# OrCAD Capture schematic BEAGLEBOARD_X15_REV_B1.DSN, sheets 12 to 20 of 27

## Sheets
12 P12_AM572x ETHERNET 1: size B; title: BeagleBoard-X15 ETHERNET PORT 1; note: BeagleBoard-X15_B.dsn
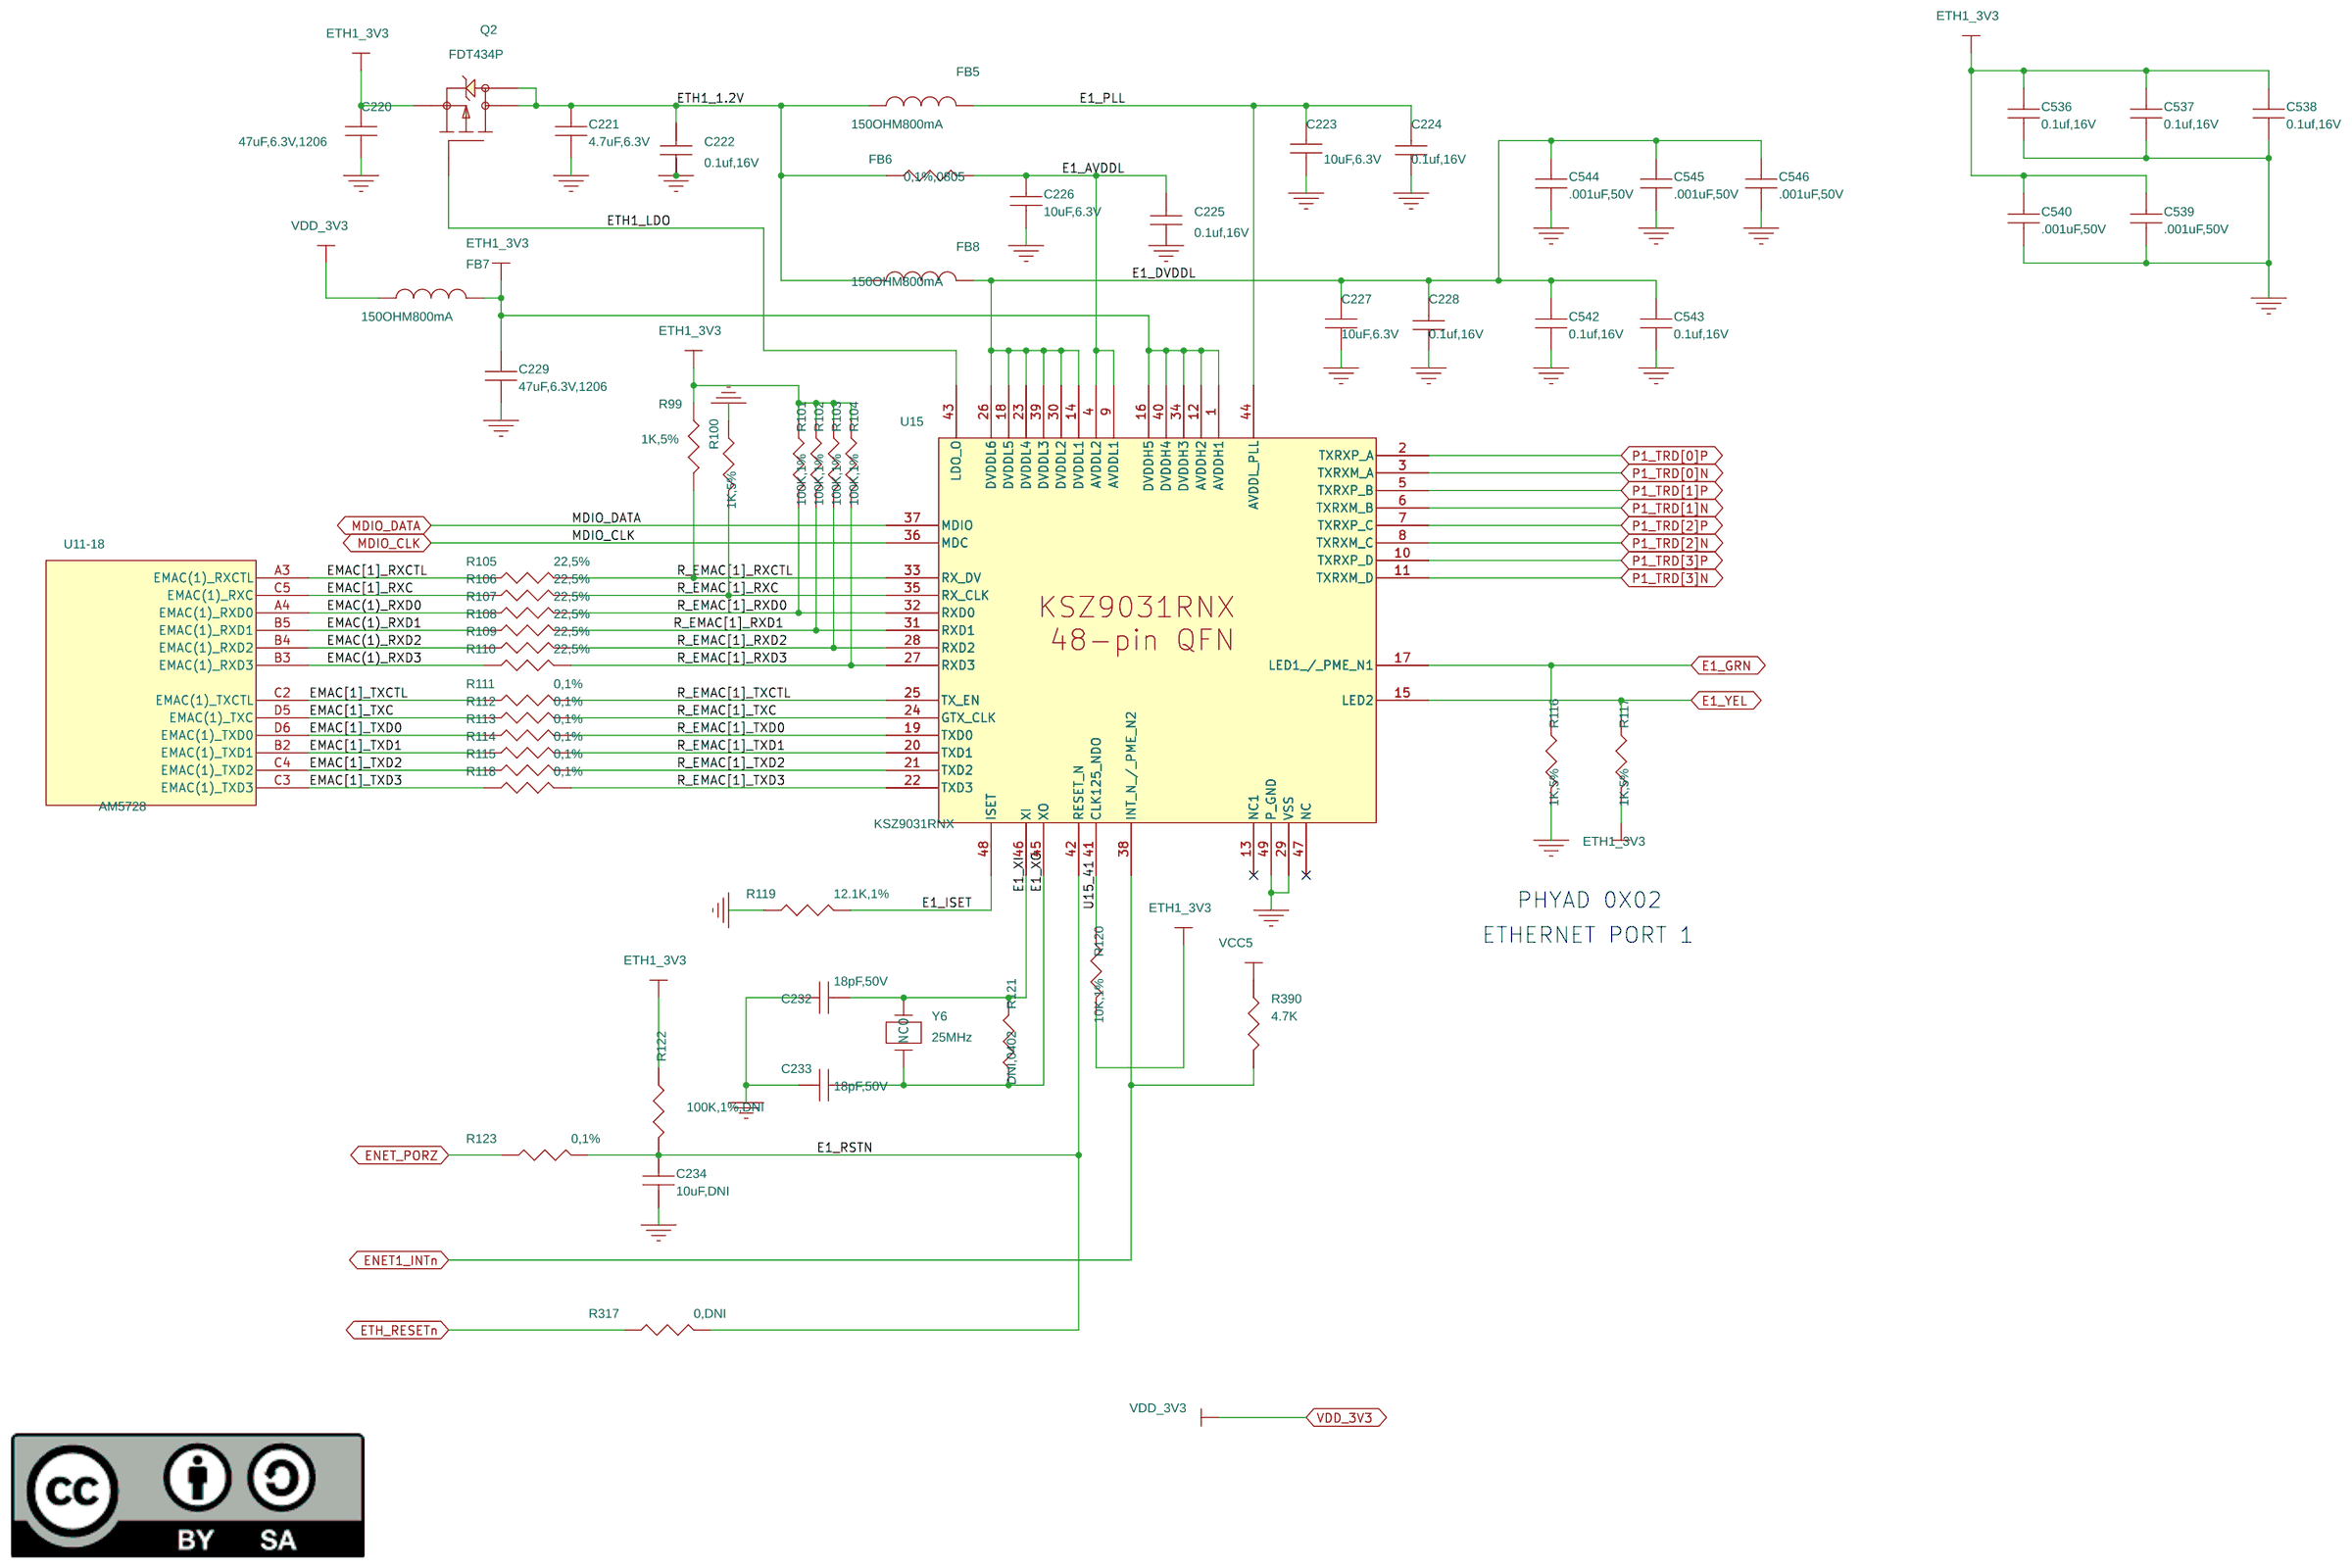
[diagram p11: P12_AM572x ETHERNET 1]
13 P13_AM572x VIN3A, LCD, BOOT: size B; title: BeagleBoard-X15 I/0, LCD, & BOOT; note: BeagleBoard-X15_B.dsn
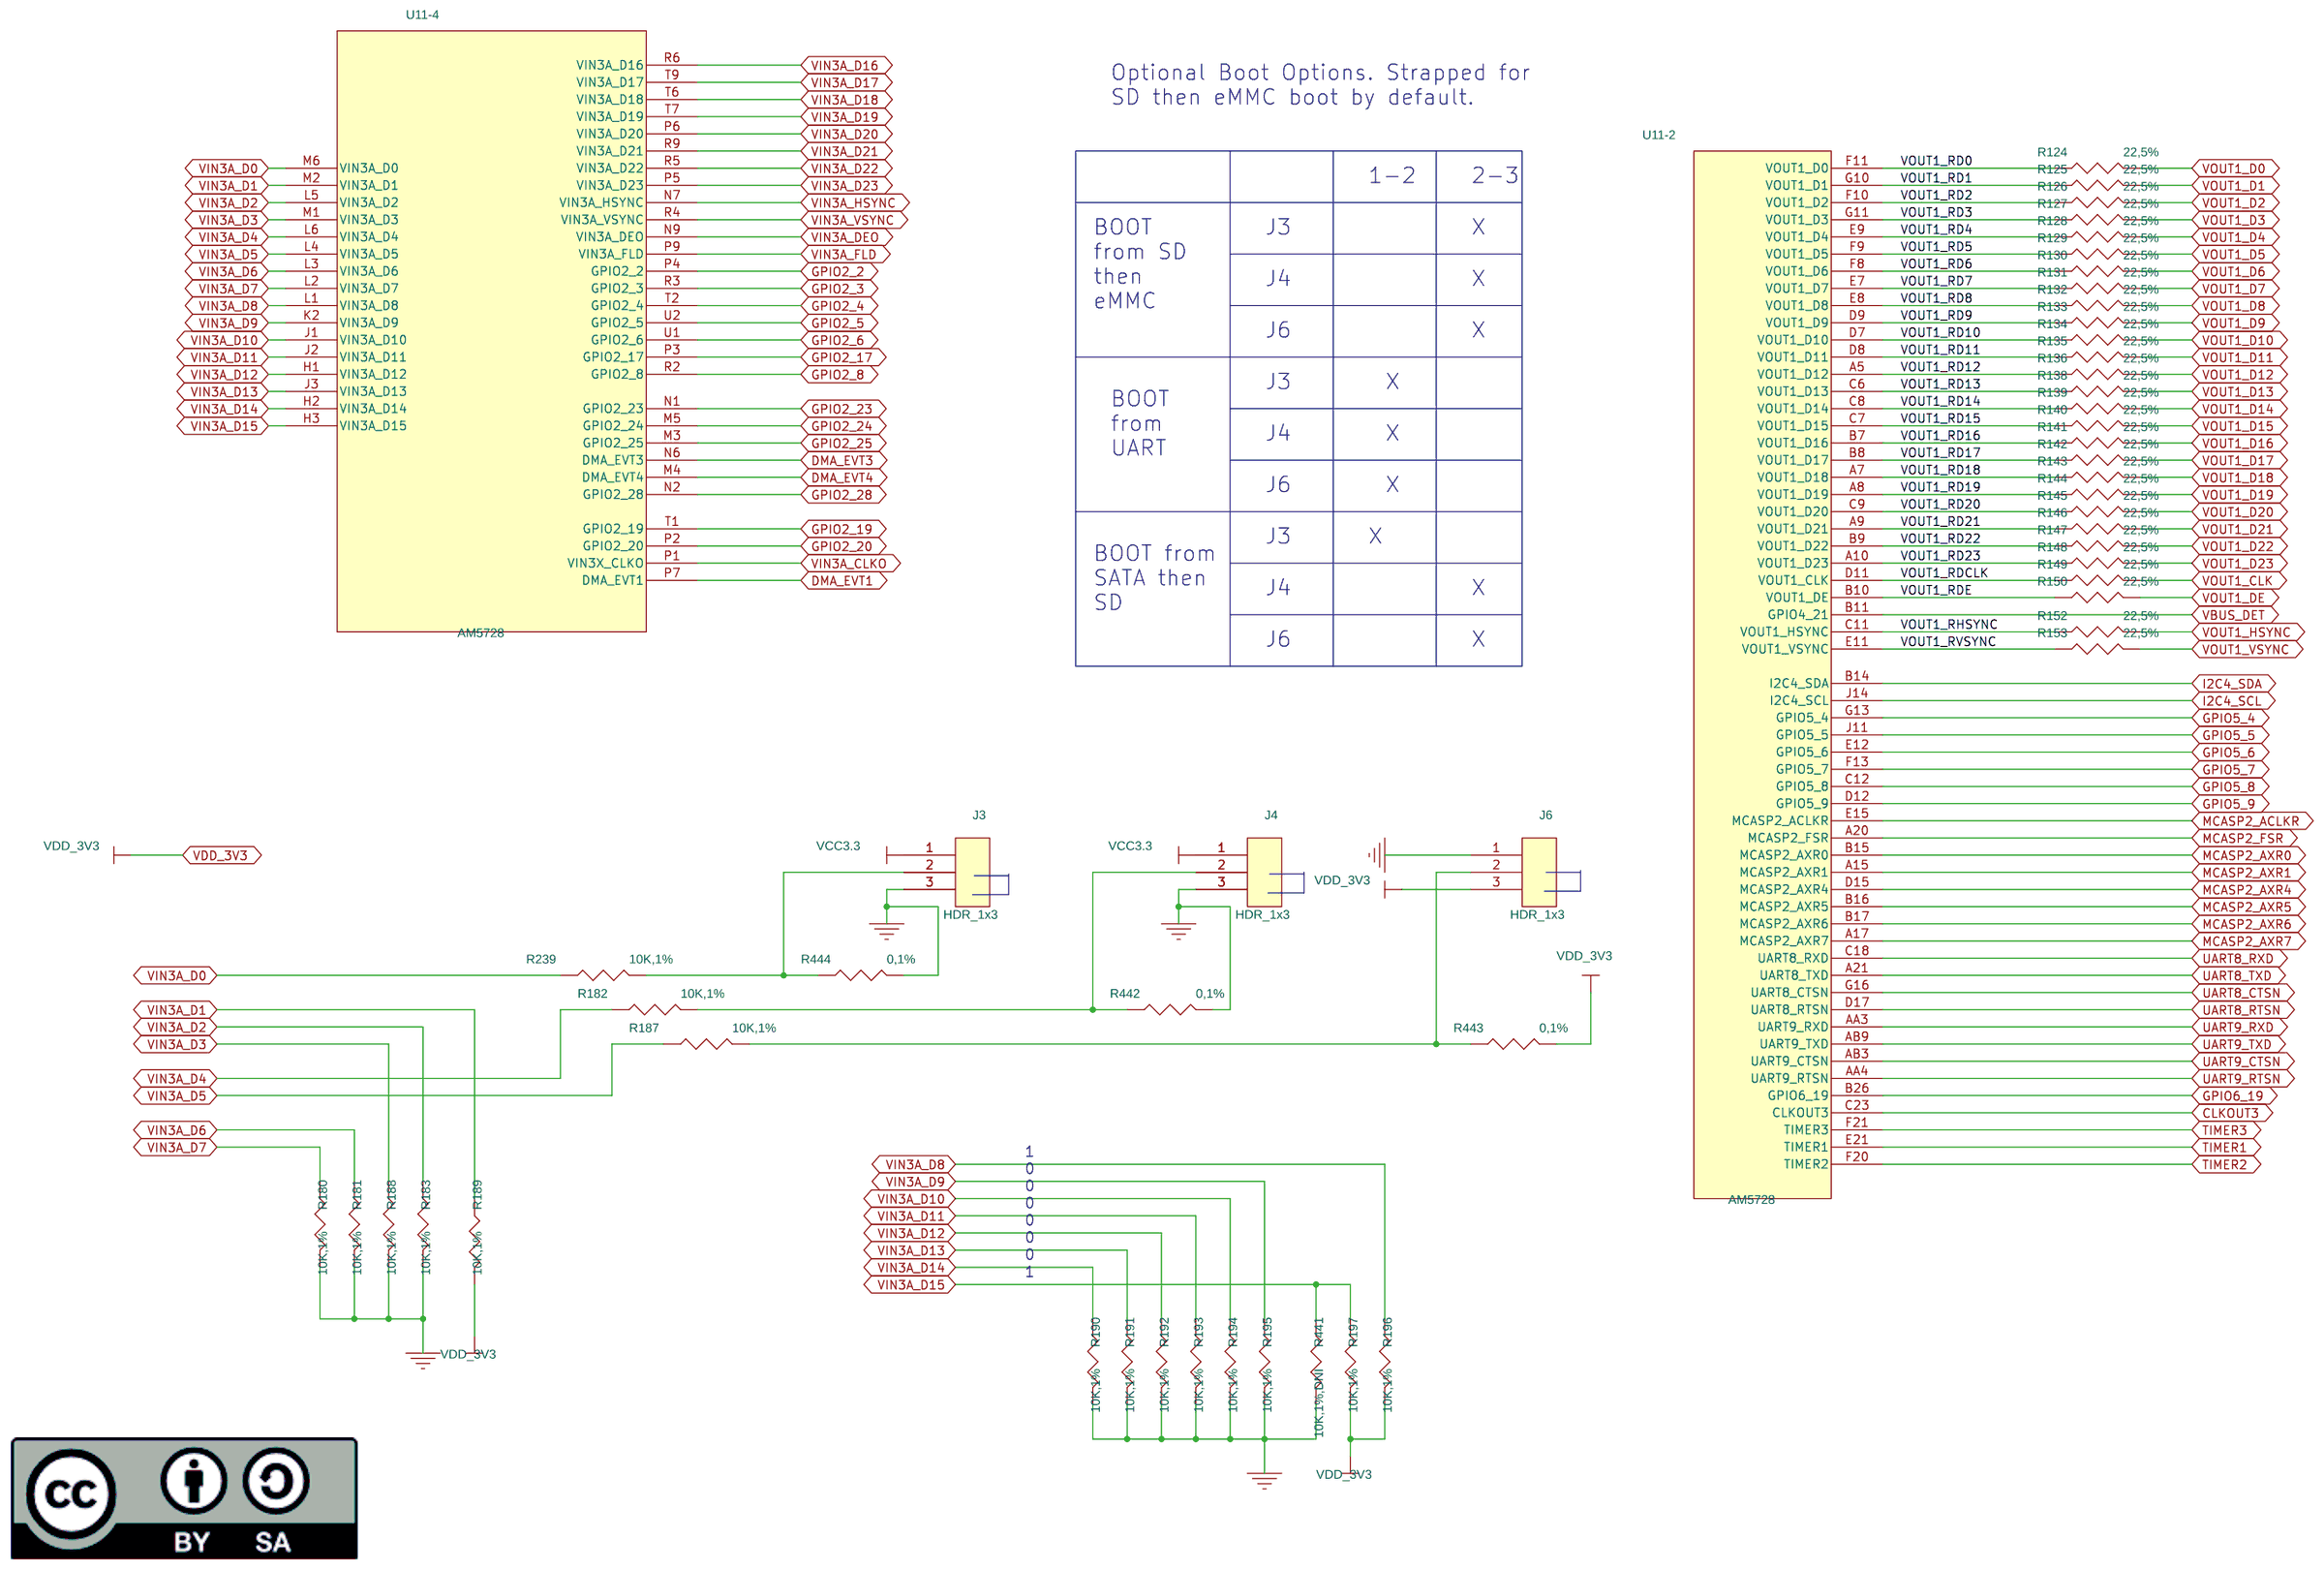
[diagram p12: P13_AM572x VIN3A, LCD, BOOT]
14 P14 AM572x USB PORTS & HUB: size B; title: BeagleBoard-X15 AM572x USB INTERFACES; note: BeagleBoard-X15_B.dsn
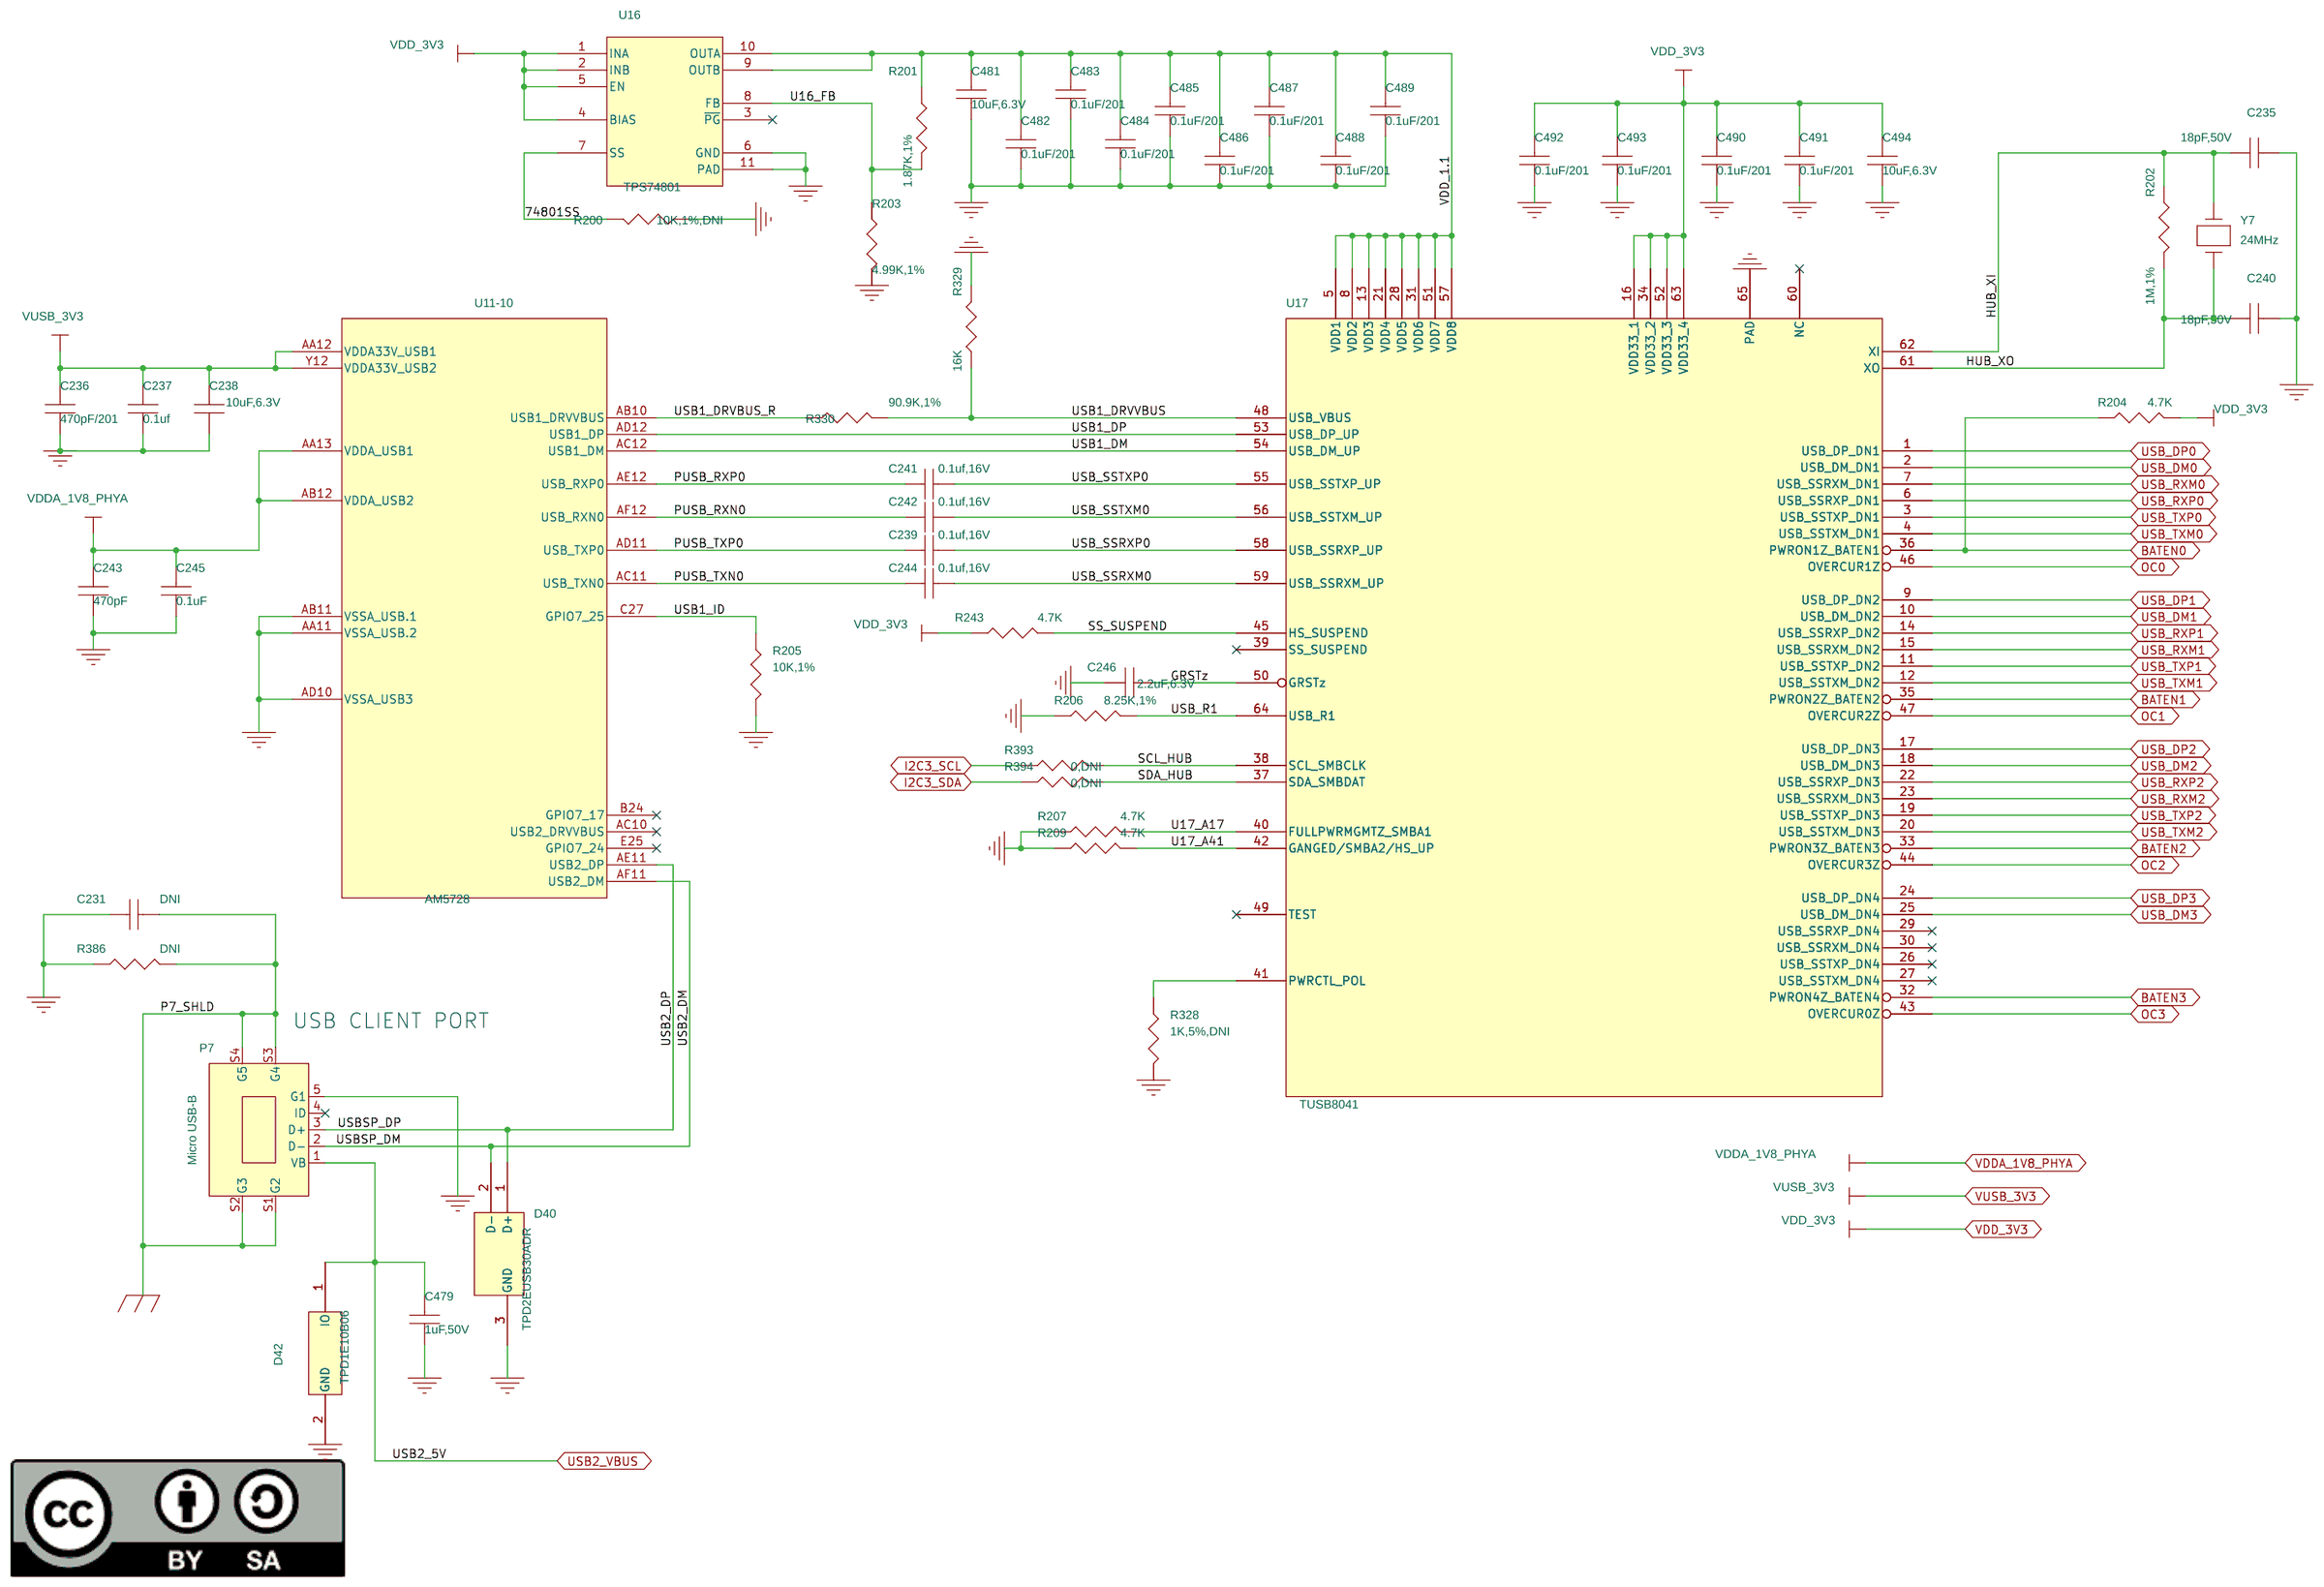
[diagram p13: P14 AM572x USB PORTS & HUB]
15 P16_AM572x, AUDIO, & DEBUG: size B; title: BeagleBoard-X15 AUDIO CODEC & DEBUG PORT; note: BeagleBoard-X15_B.dsn
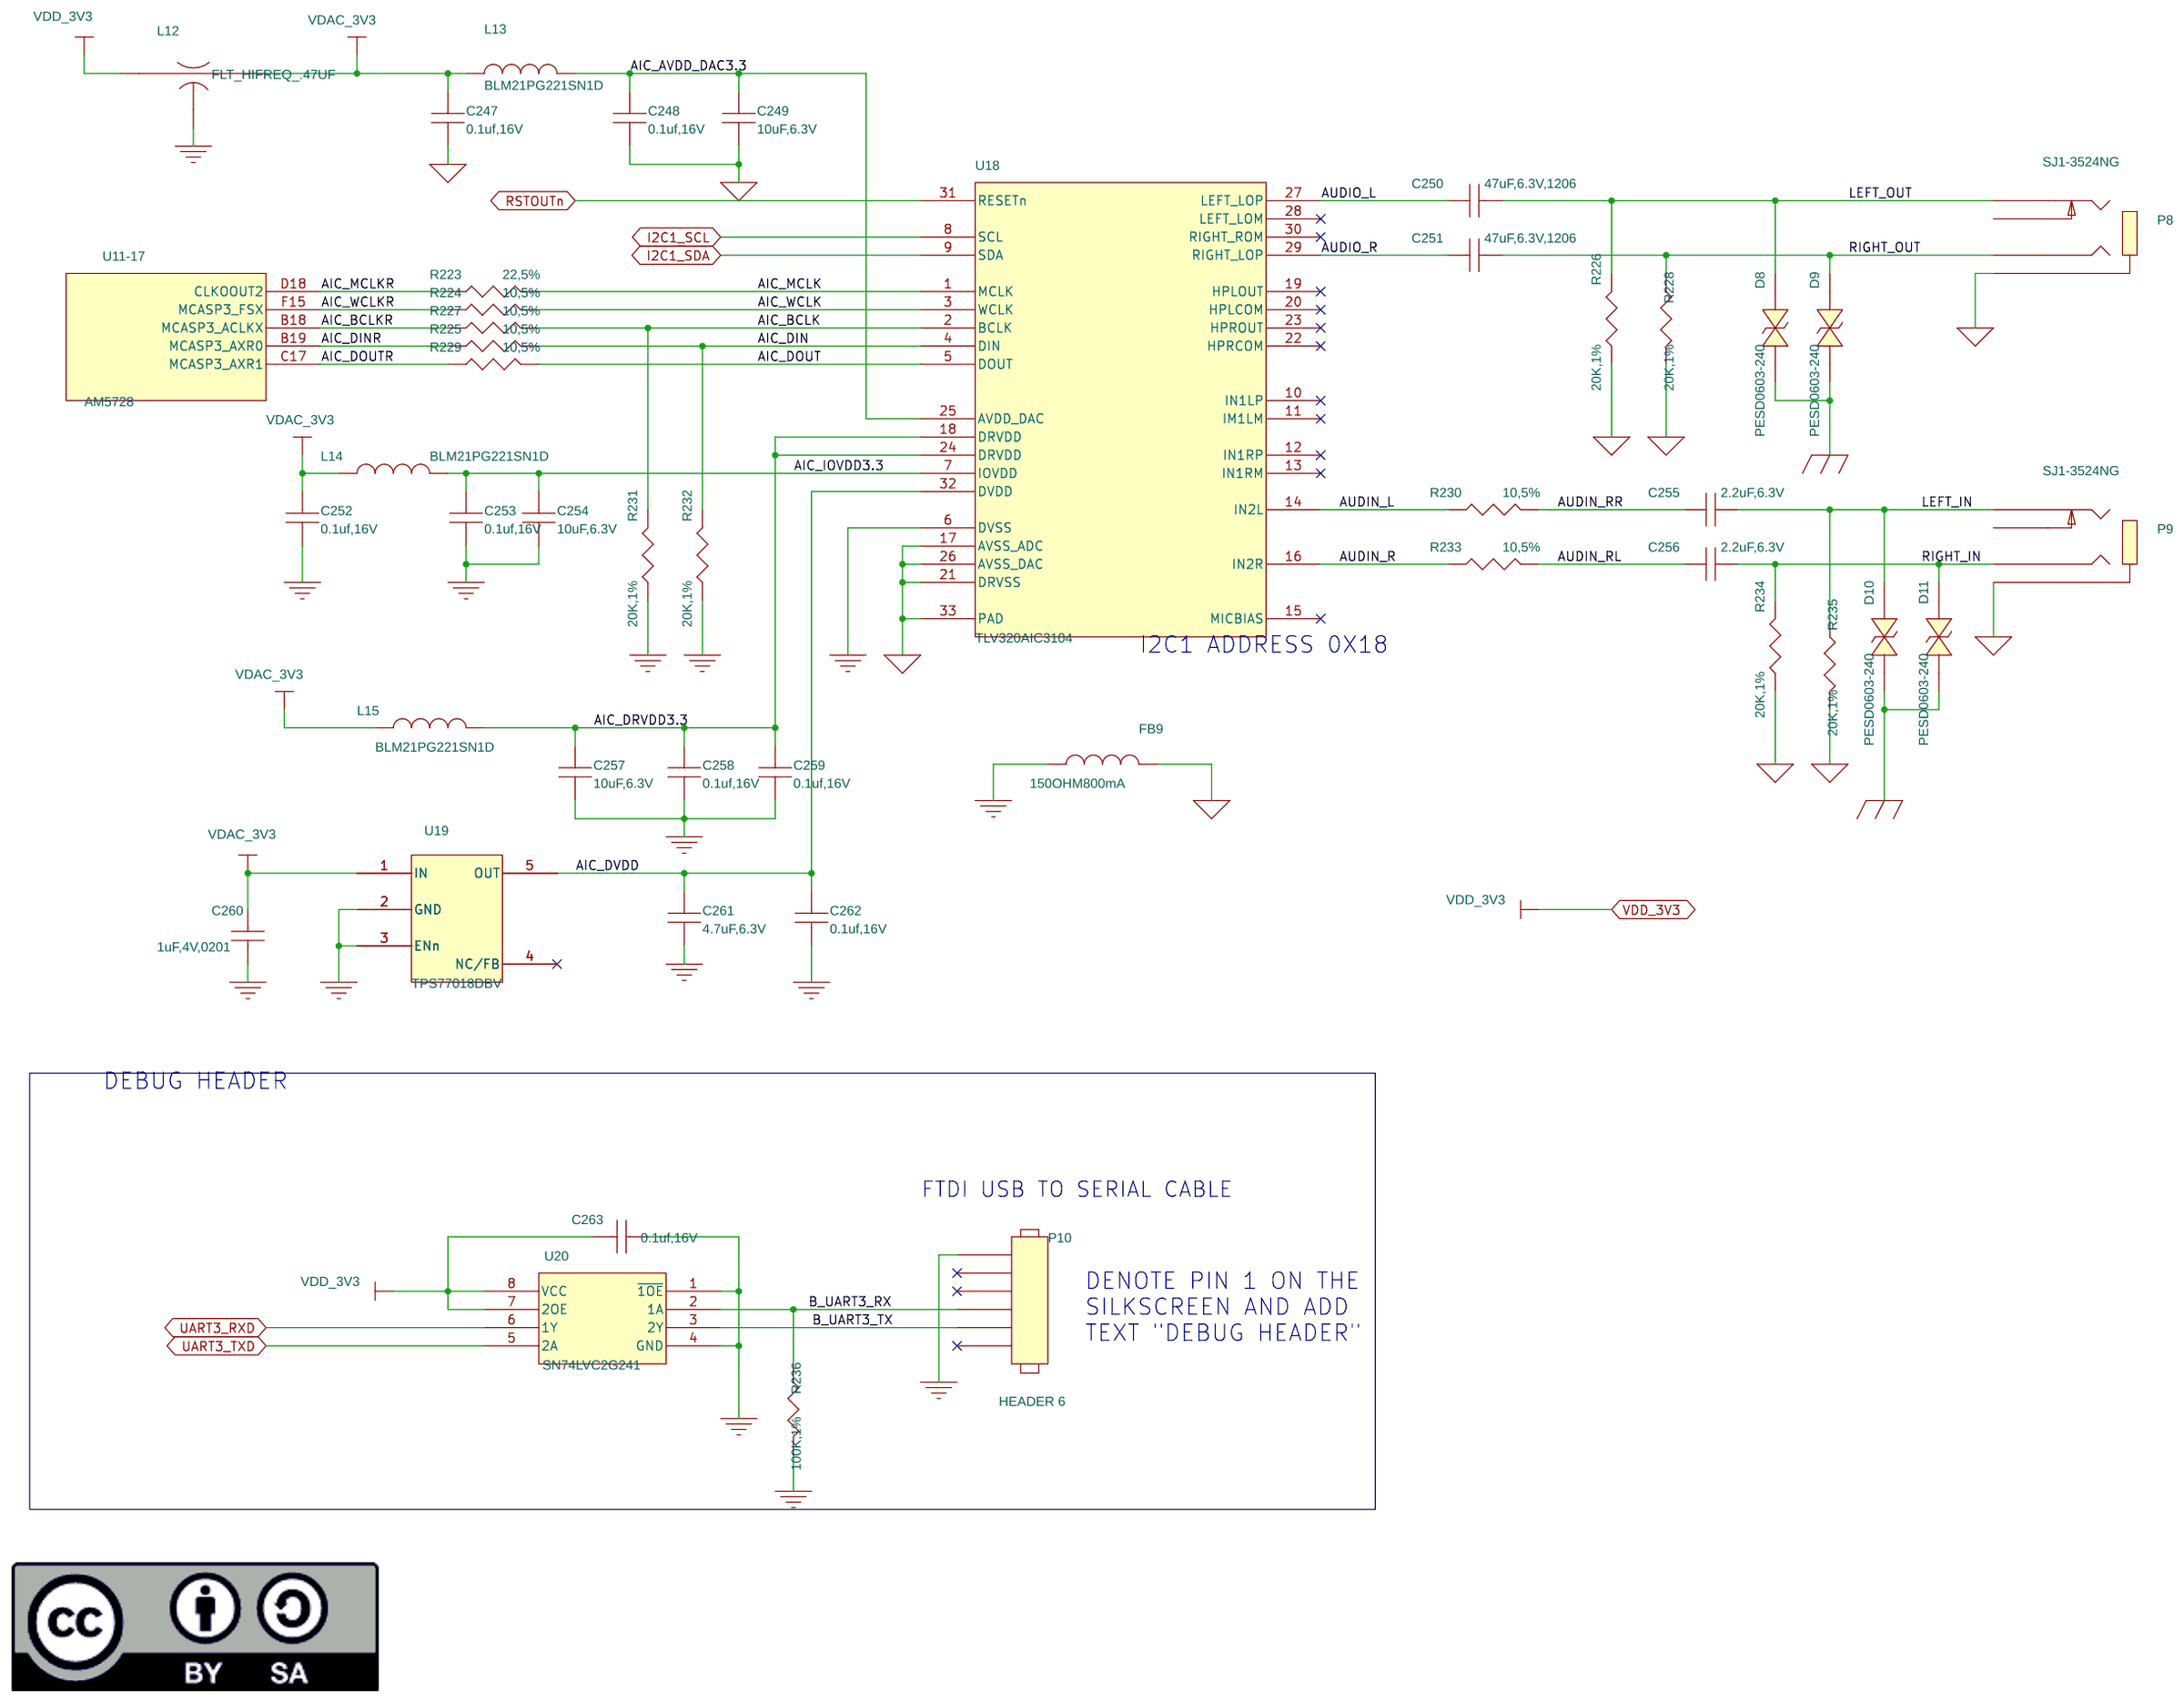
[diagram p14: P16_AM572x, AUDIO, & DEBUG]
16 P17_AM572x_HDMI PORT: size B; title: BeagleBoard-X15 HDMI PORT; note: BeagleBoard-X15_B.dsn
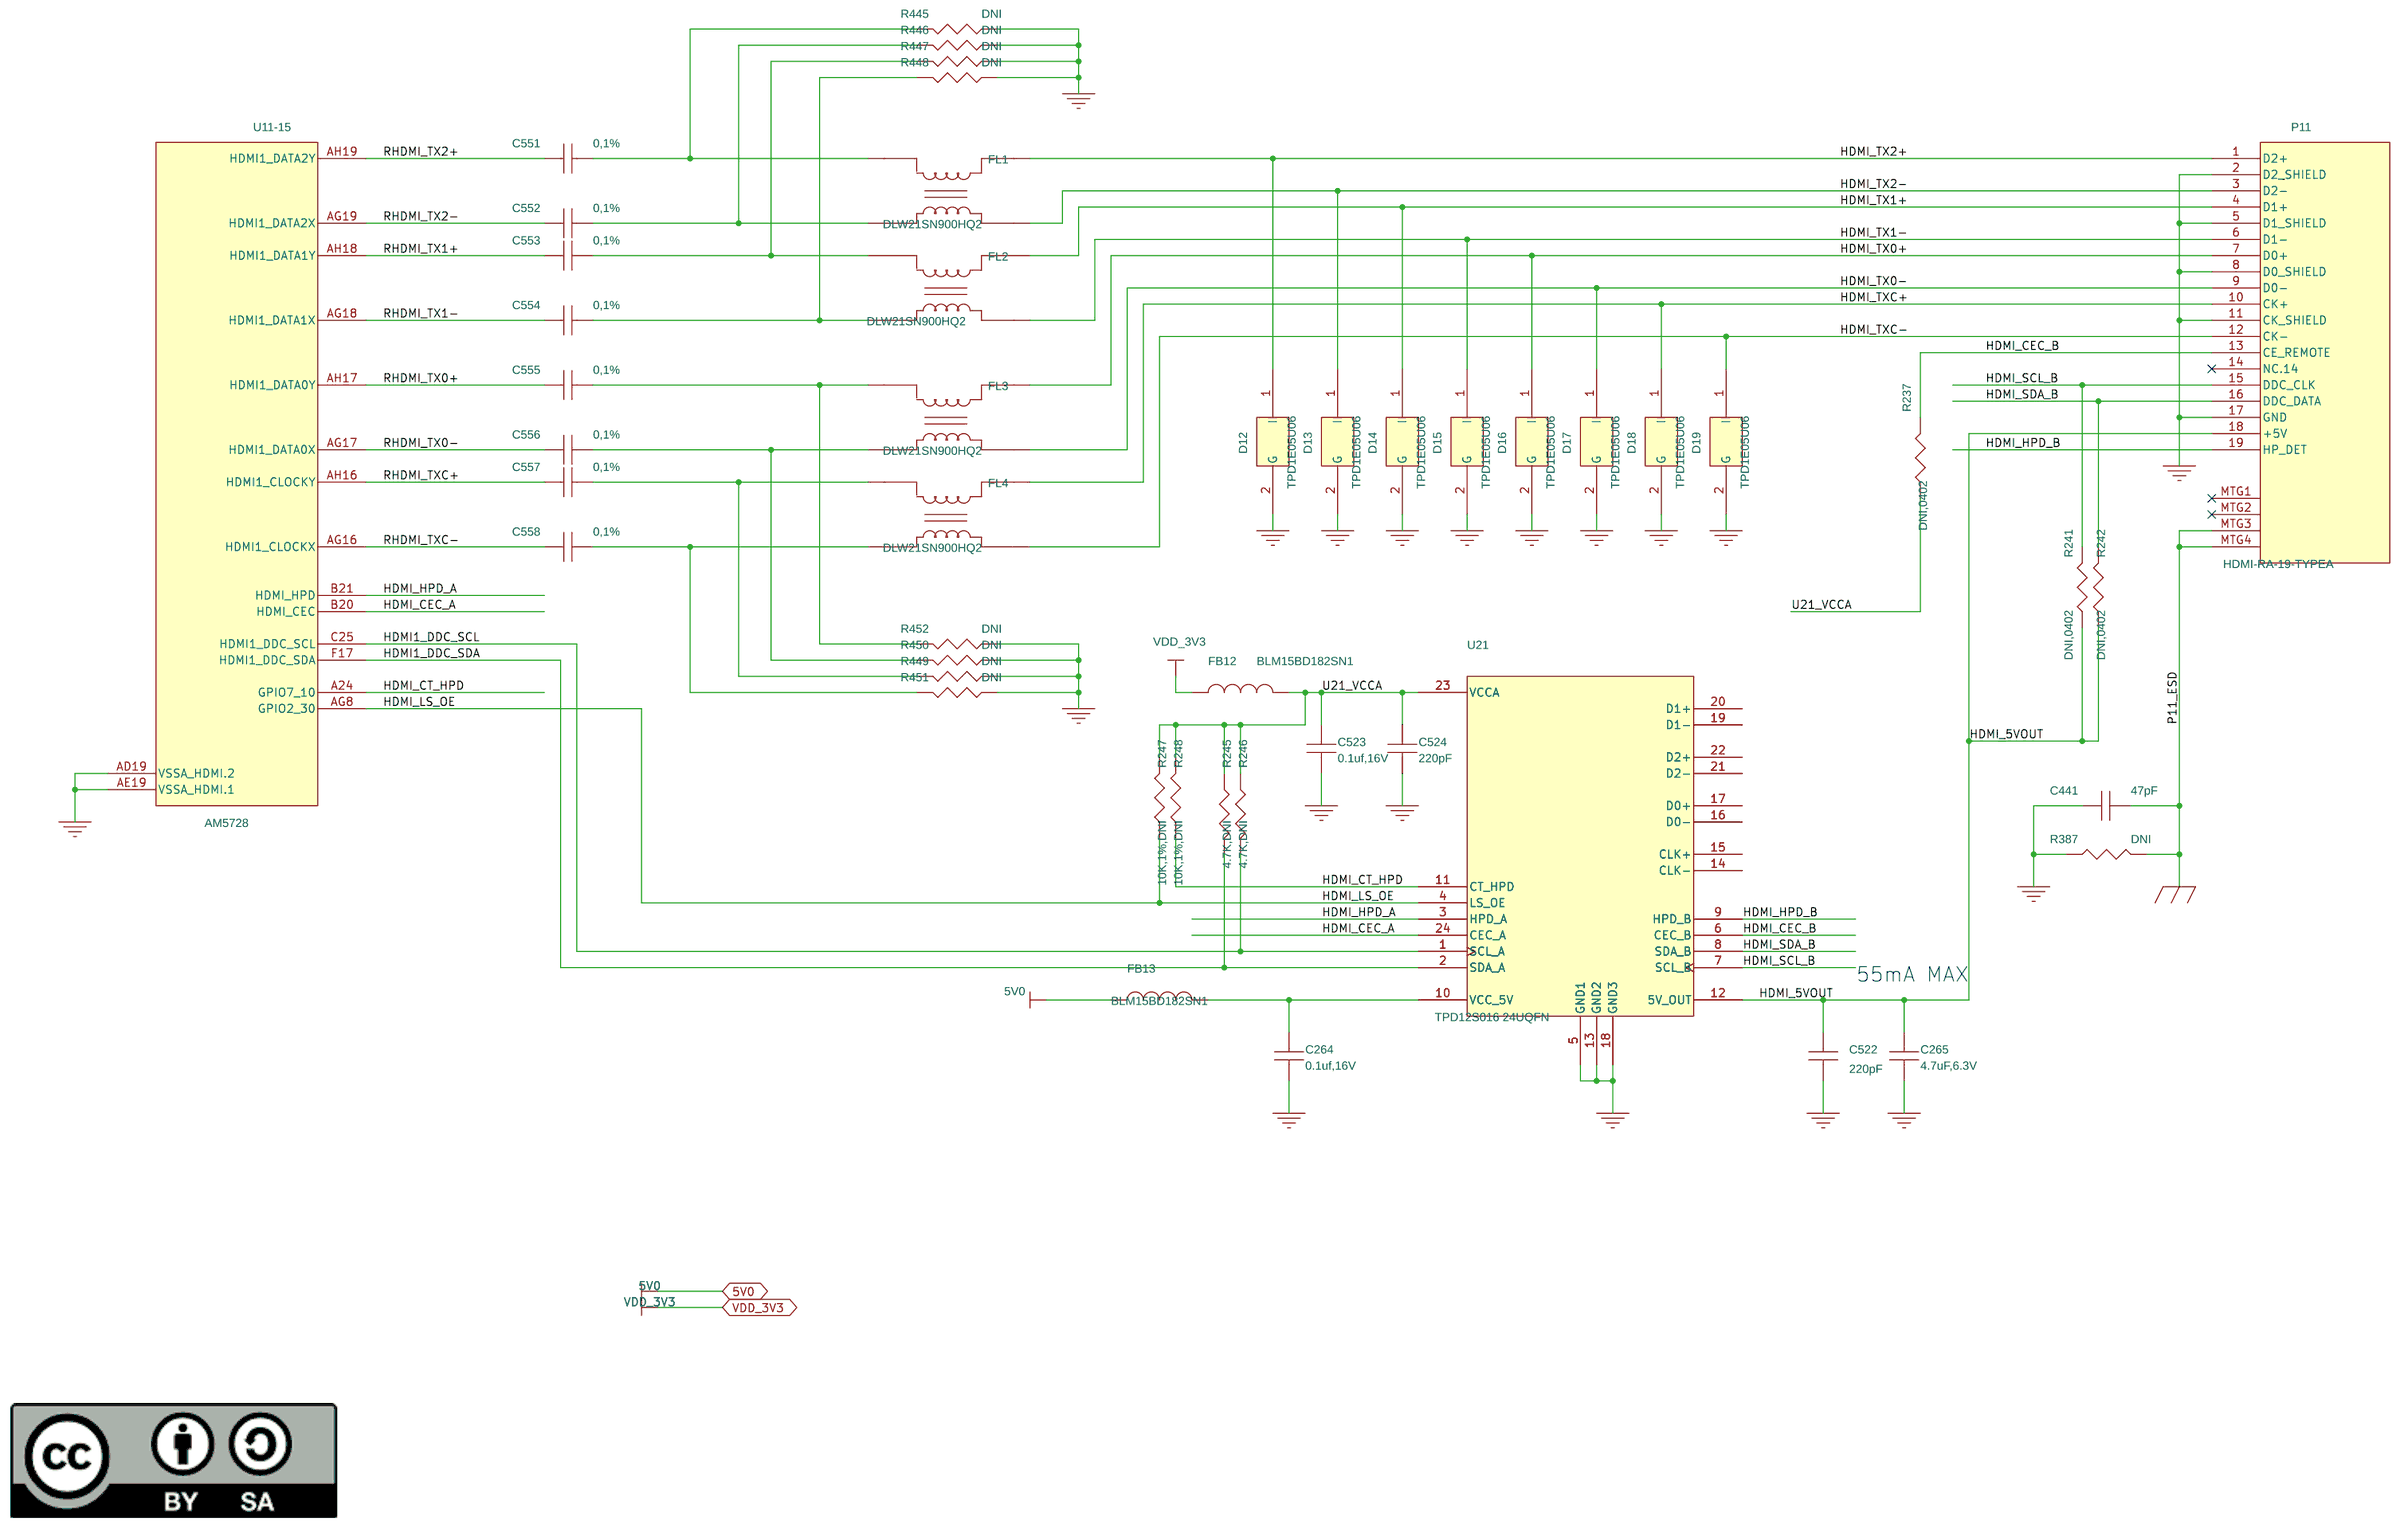
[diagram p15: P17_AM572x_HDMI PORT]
17 P18_AM572x eMMC, MMC3 & uSD: size B; title: BeagleBoard-X15 eMMC & microSD; note: BeagleBoard-X15_B.dsn
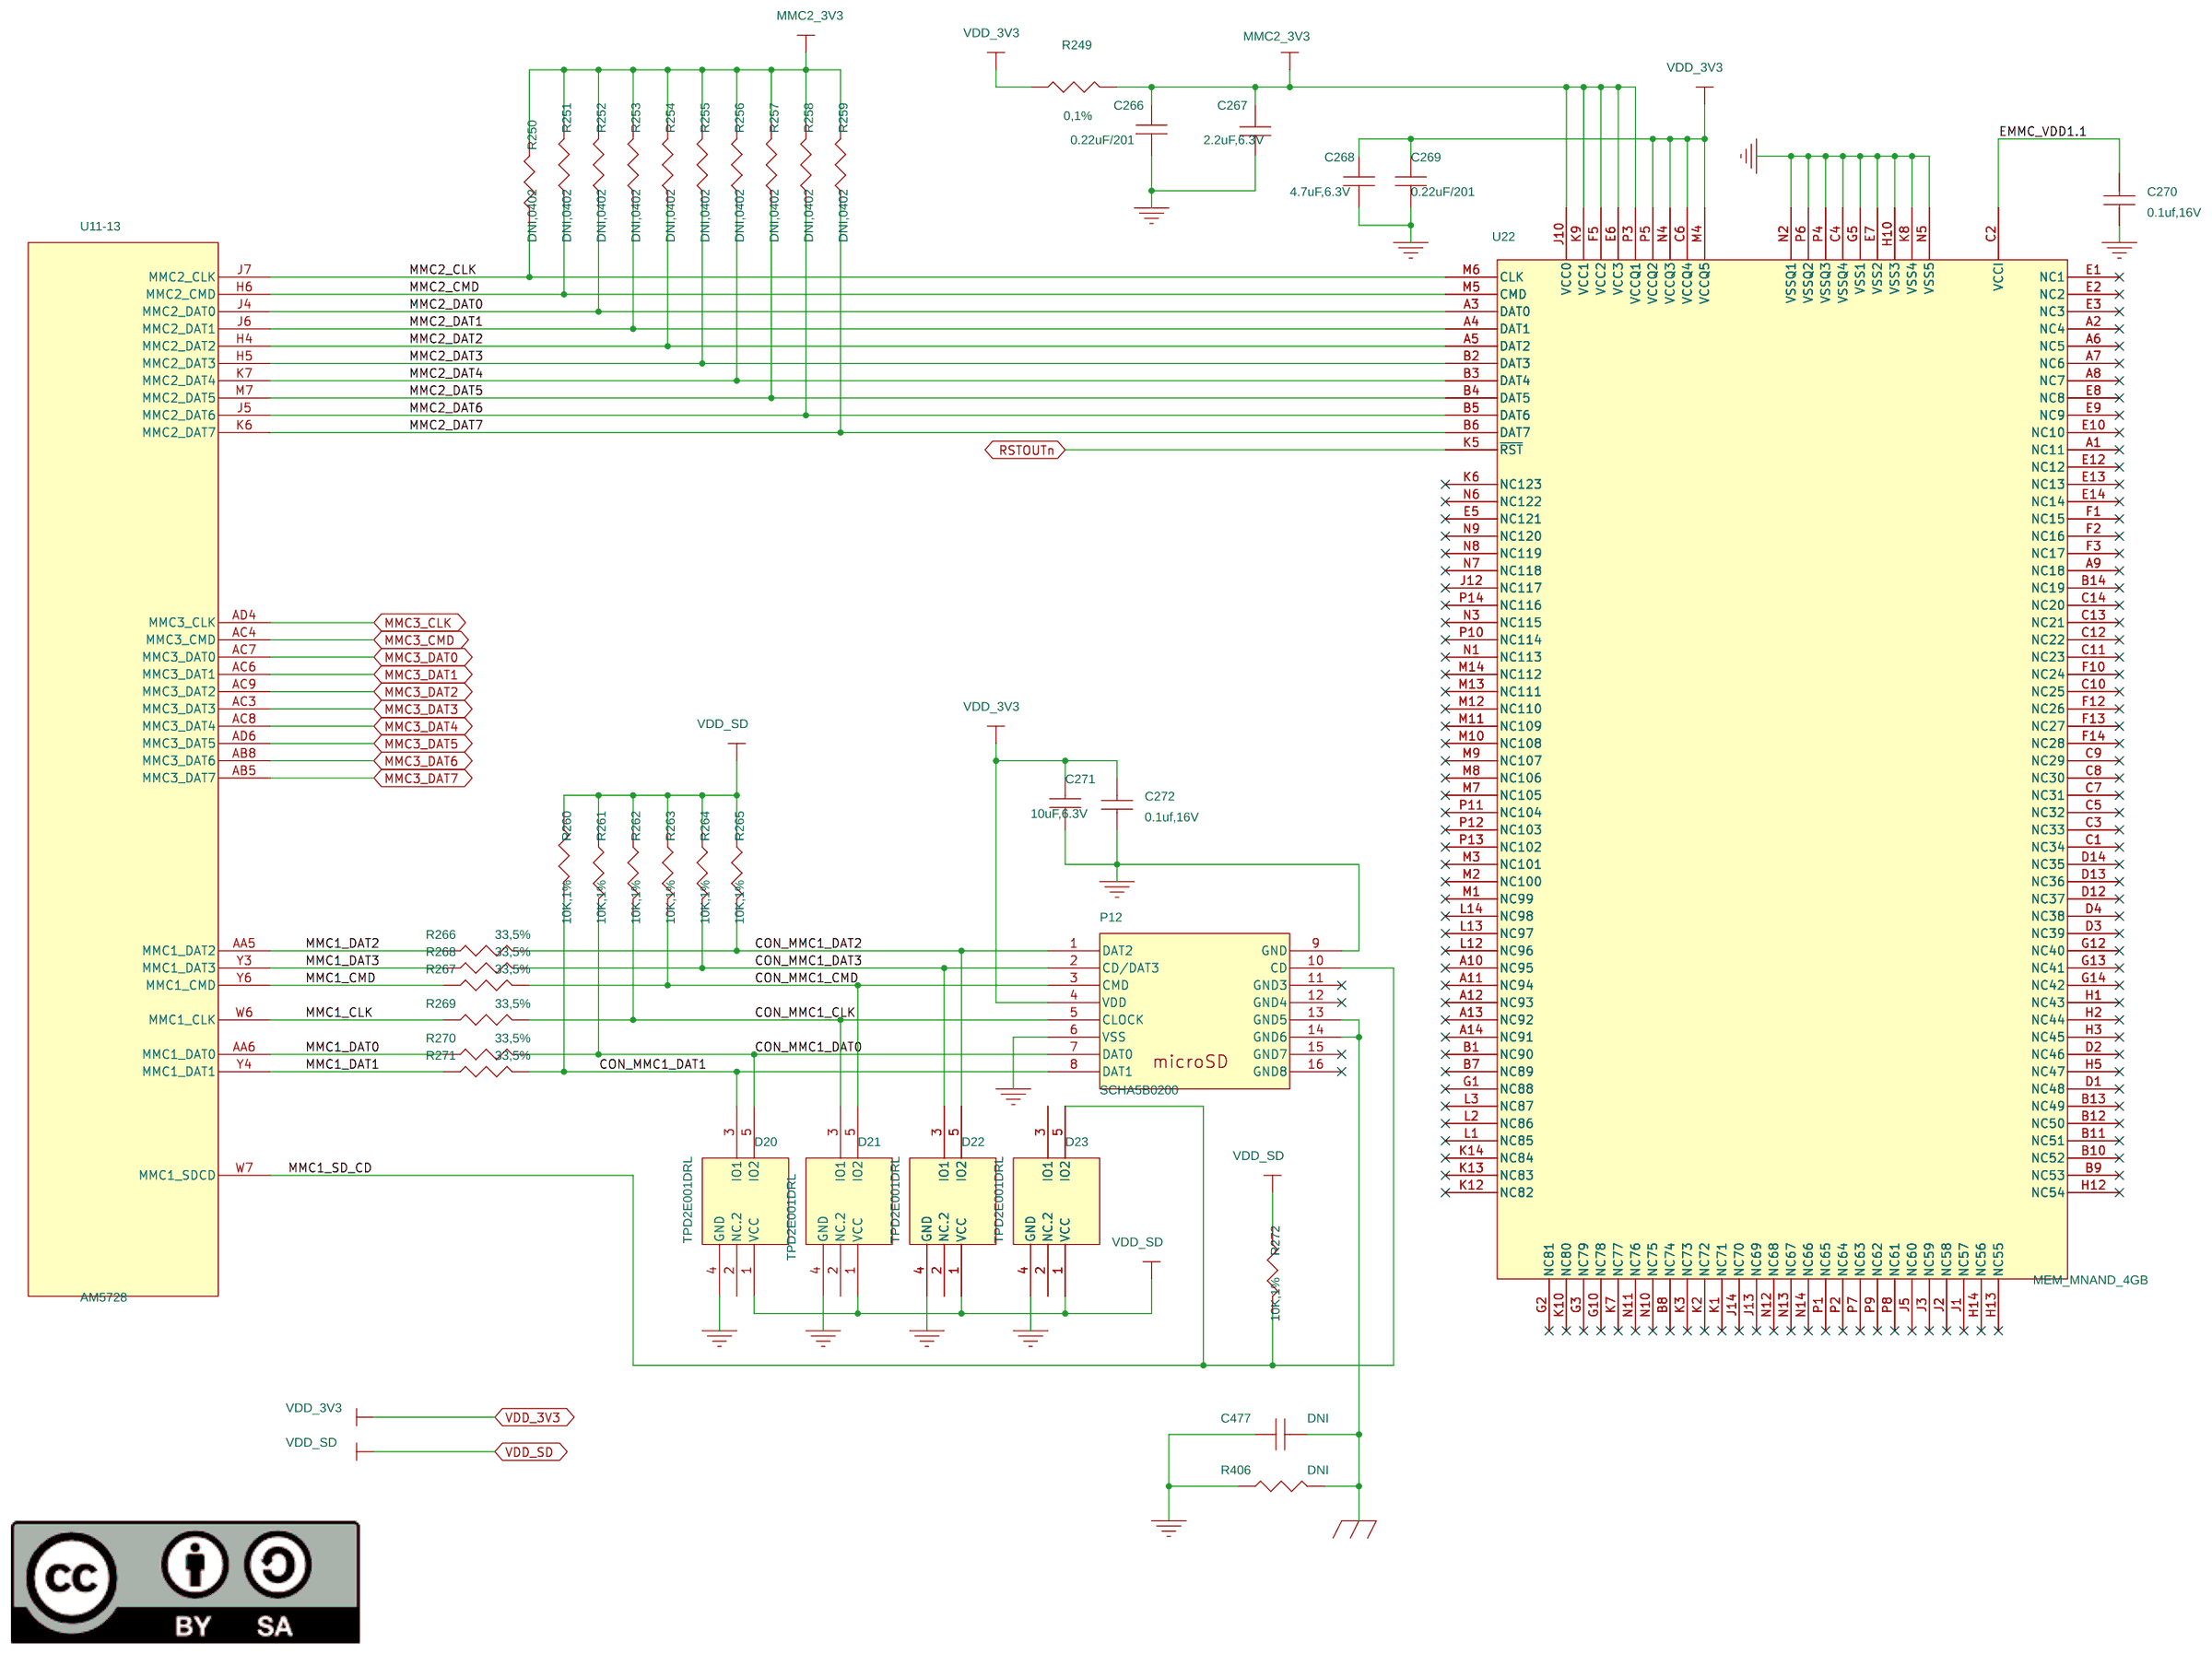
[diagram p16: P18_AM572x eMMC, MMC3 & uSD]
18 P19_AM572x DDR INTERFACE 1: size B; title: BeagleBoard-X15 DDR INTERFACE 1; note: BeagleBoard-X15_B.dsn
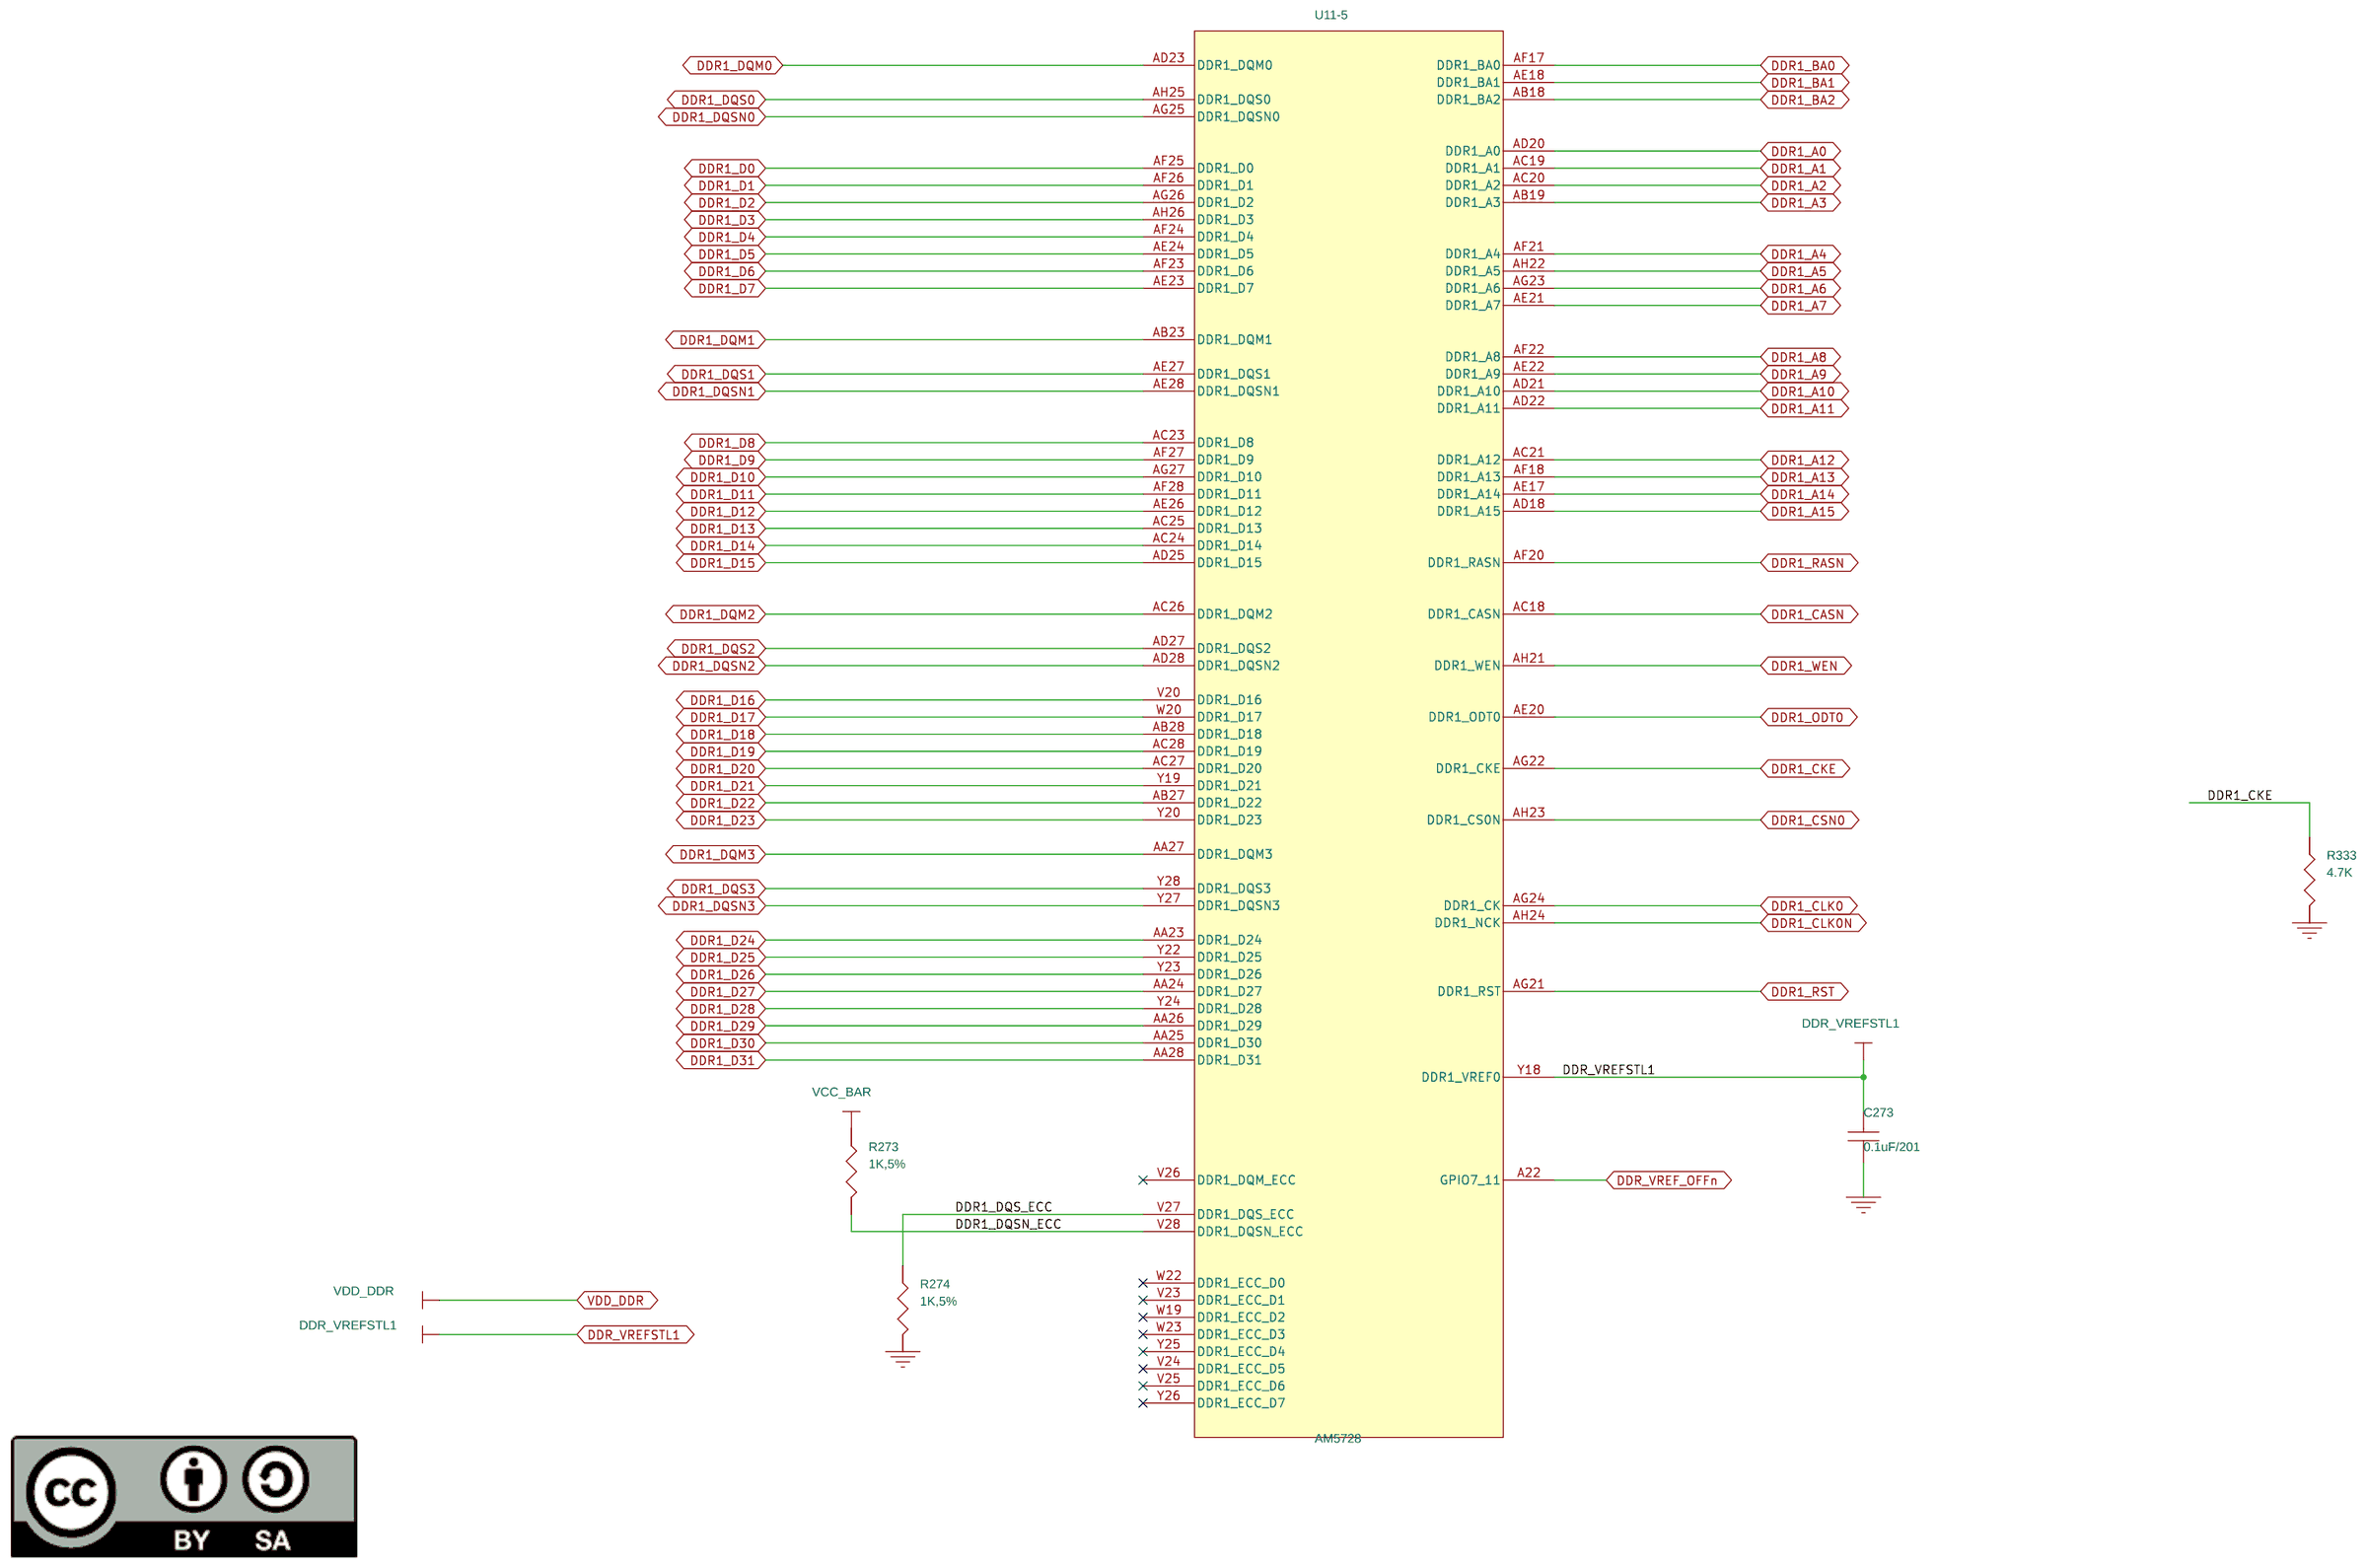
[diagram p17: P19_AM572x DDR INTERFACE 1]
19 P20_AM572x DDR INTERFACE 2: size B; title: BeagleBoard-X15 DDR INTERFACE2; note: BeagleBoard-X15_B.dsn
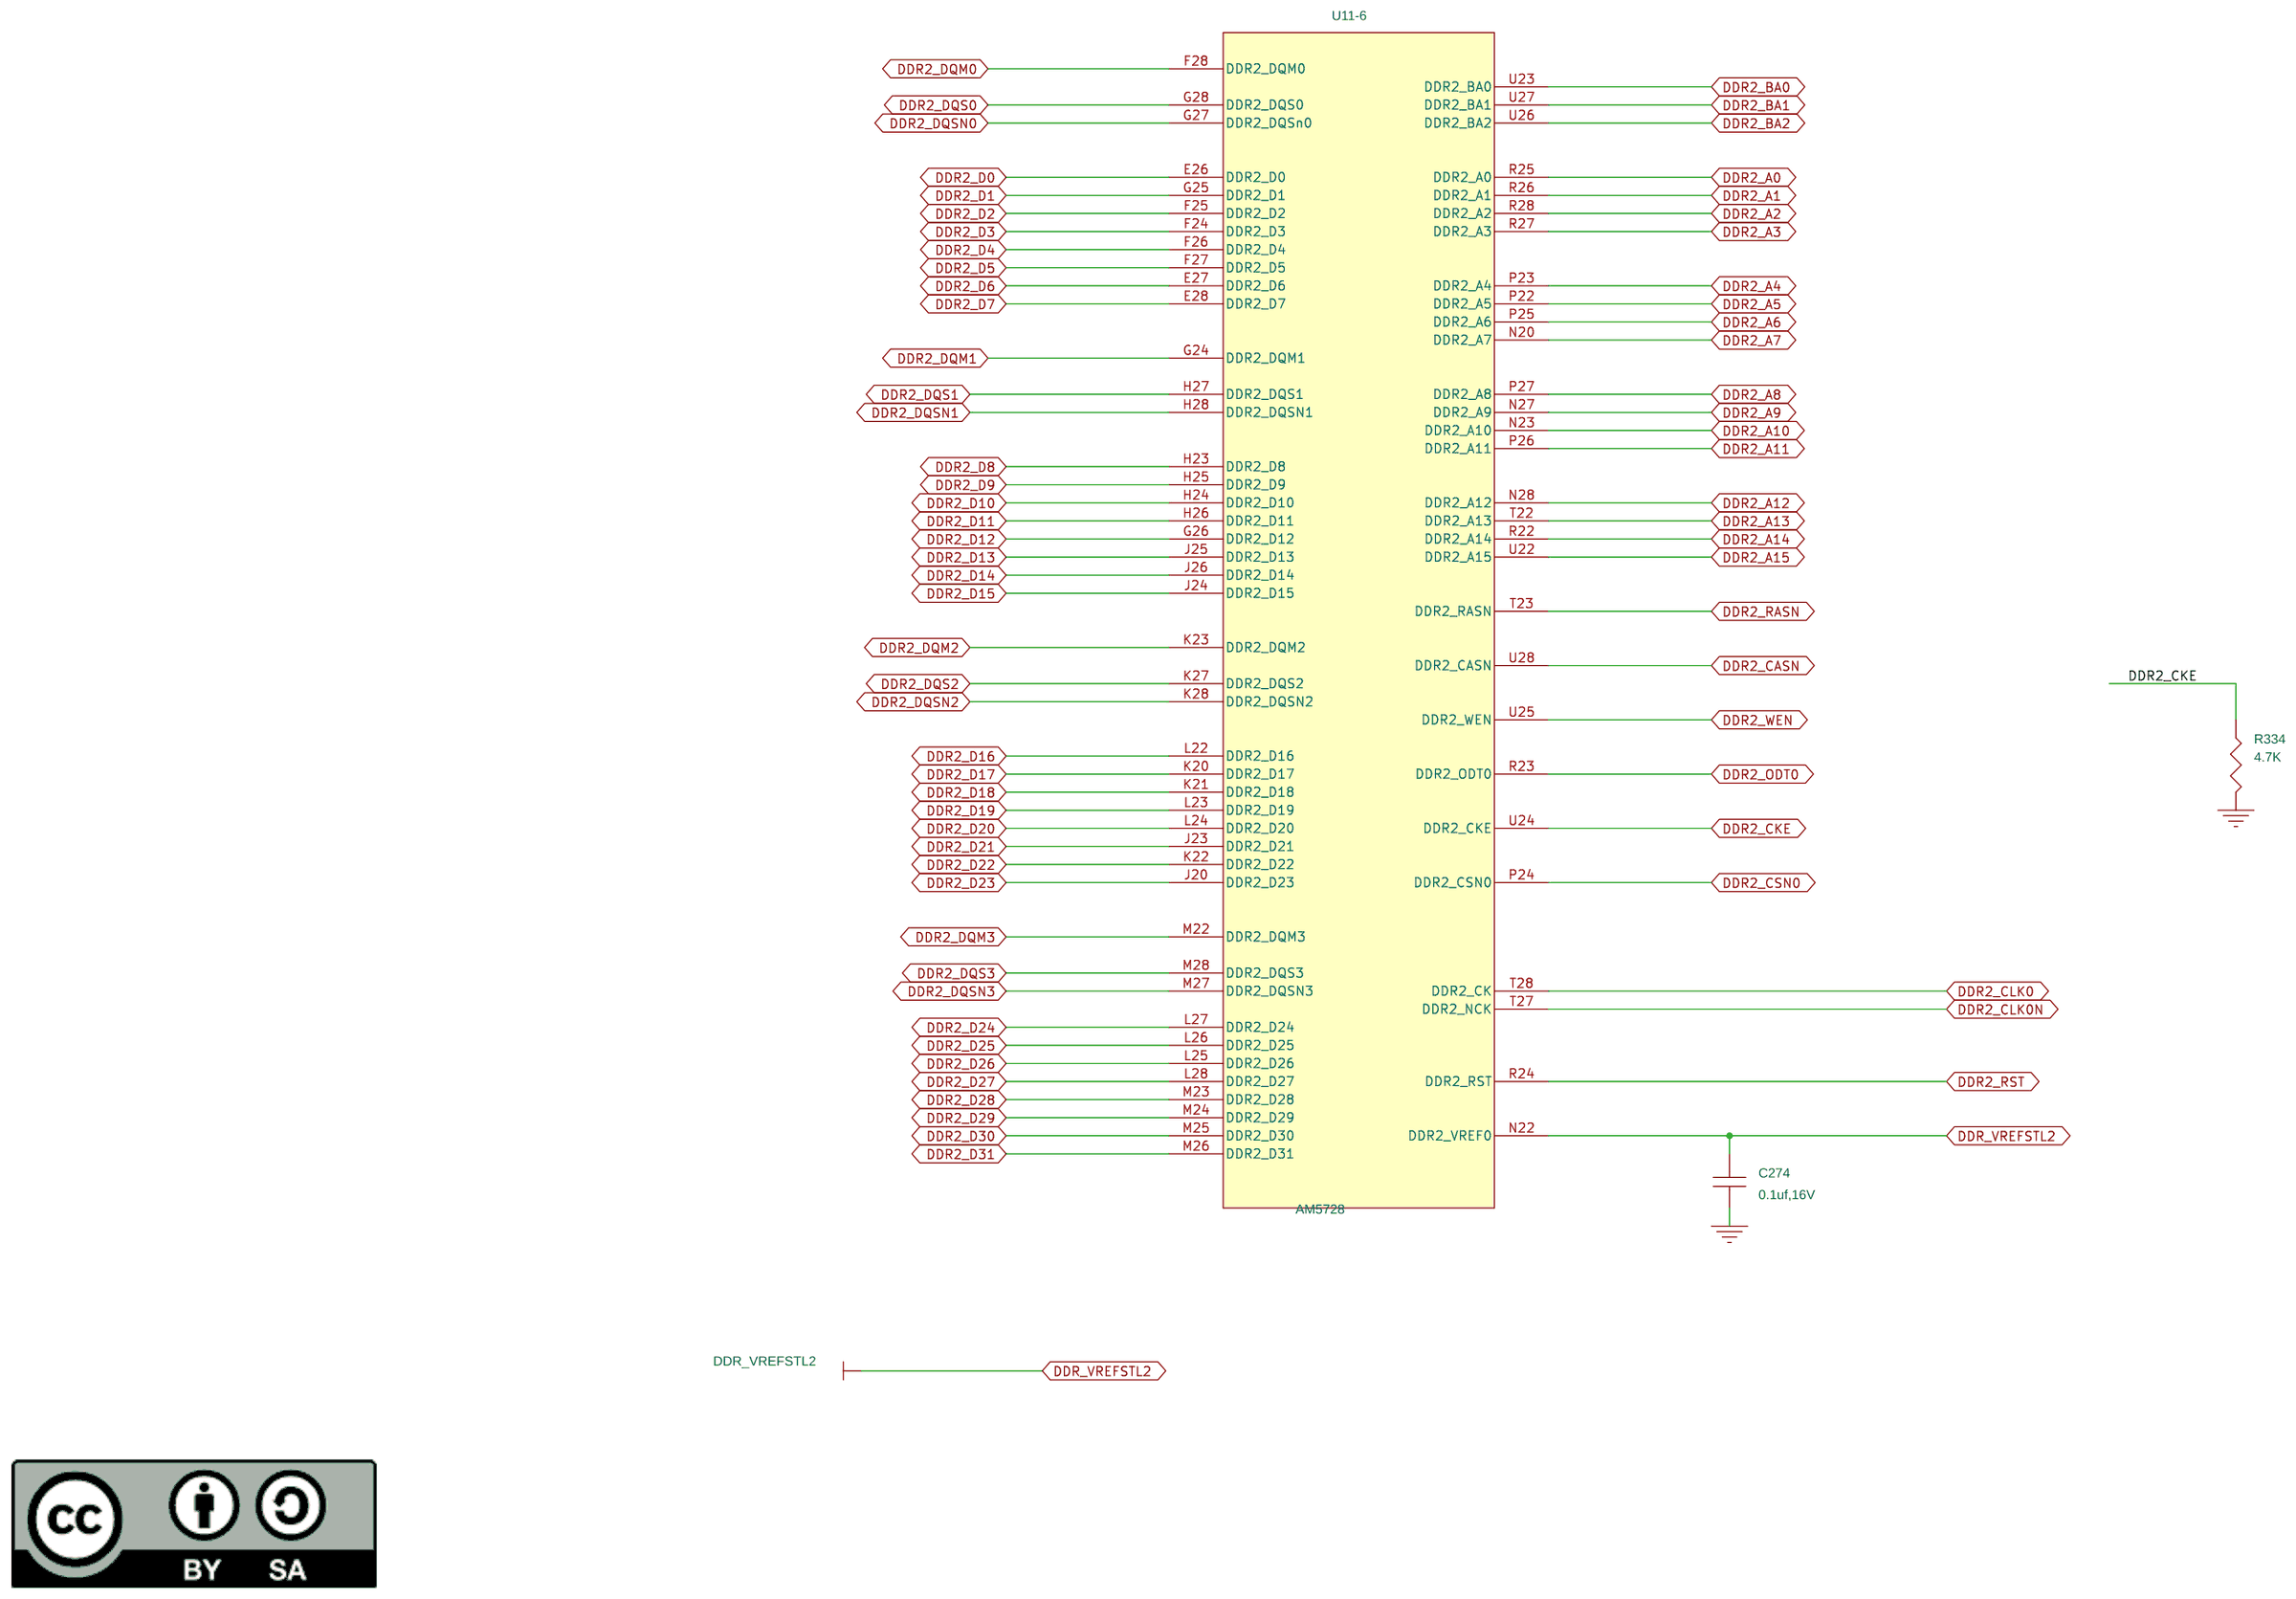
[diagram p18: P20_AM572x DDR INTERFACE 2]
20 P21_DDR3  BANK 1: size B; title: BeagleBoard-X15 DDR BANK 1; note: BeagleBoard-X15_B.dsn
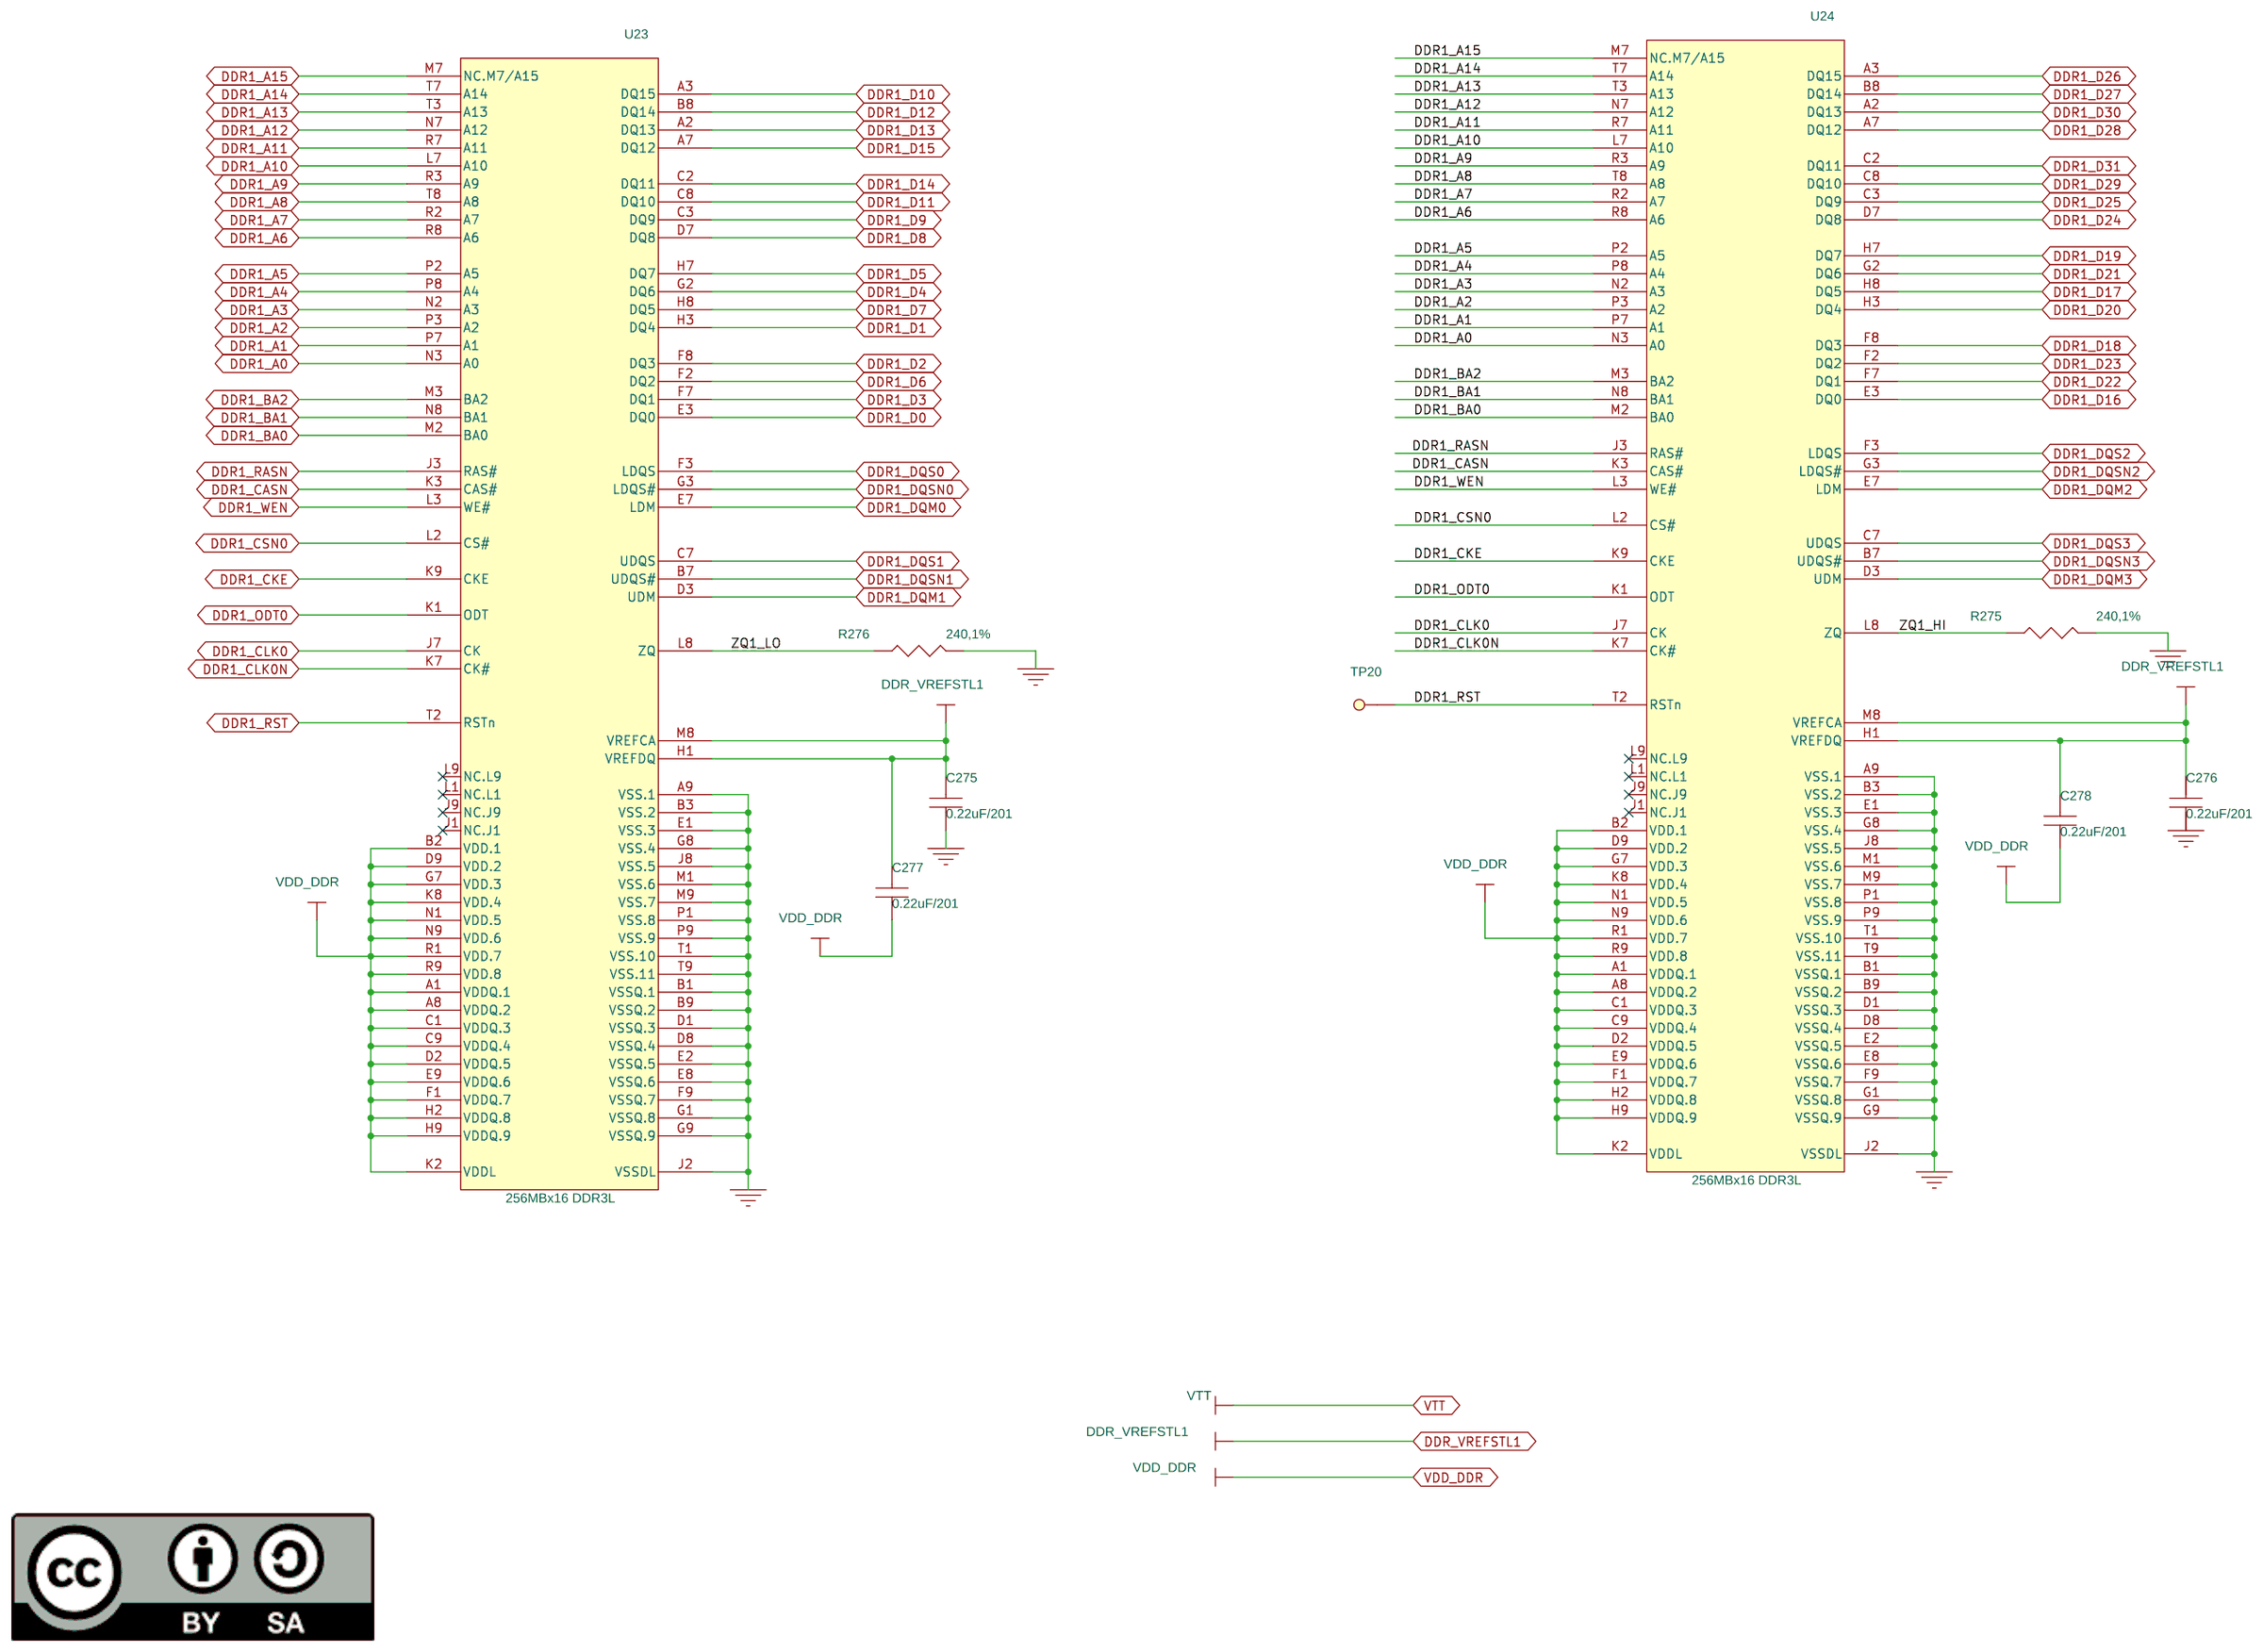
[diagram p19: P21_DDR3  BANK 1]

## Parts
sheet P12_AM572x ETHERNET 1
C220  47uF,6.3V,1206  [1206]
C221  4.7uF,6.3V  [402]
C222  0.1uf,16V  [402]
C223  10uF,6.3V  [603]
C224  0.1uf,16V  [402]
C225  0.1uf,16V  [402]
C226  10uF,6.3V  [603]
C227  10uF,6.3V  [603]
C228  0.1uf,16V  [402]
C229  47uF,6.3V,1206  [1206]
C232  18pF,50V  [402]
C233  18pF,50V  [402]
C234  10uF,DNI  [603]
C536  0.1uf,16V  [402]
C537  0.1uf,16V  [402]
C538  0.1uf,16V  [402]
C539  .001uF,50V  [402]
C540  .001uF,50V  [402]
C542  0.1uf,16V  [402]
C543  0.1uf,16V  [402]
C544  .001uF,50V  [402]
C545  .001uF,50V  [402]
C546  .001uF,50V  [402]
FB5  150OHM800mA  [805]
FB6  0,1%,0805  [805]
FB7  150OHM800mA  [805]
FB8  150OHM800mA  [805]
Q2  FDT434P  [SOT223-1]
R99  1K,5%  [402]
R100  1K,5%  [402]
R101  100K,1%  [402]
R102  100K,1%  [402]
R103  100K,1%  [402]
R104  100K,1%  [402]
R105  22,5%  [402]
R106  22,5%  [402]
R107  22,5%  [402]
R108  22,5%  [402]
R109  22,5%  [402]
R110  22,5%  [402]
R111  0,1%  [402]
R112  0,1%  [402]
R113  0,1%  [402]
R114  0,1%  [402]
R115  0,1%  [402]
R116  1K,5%  [402]
R117  1K,5%  [402]
R118  0,1%  [402]
R119  12.1K,1%  [402]
R120  10K,1%  [402]
R121  DNI,0402  [402]
R122  100K,1%,DNI  [402]
R123  0,1%  [402]
R317  0,DNI  [402]
R390  4.7K  [402]
U15  KSZ9031RNX  [QFN48]
Y6  25MHz  [xtal_3p2x5smd]
sheet P13_AM572x VIN3A, LCD, BOOT
J3  HDR_1x3  [SIP3]
J4  HDR_1x3  [SIP3]
J6  HDR_1x3  [SIP3]
R124  22,5%  [402]
R125  22,5%  [402]
R126  22,5%  [402]
R127  22,5%  [402]
R128  22,5%  [402]
R129  22,5%  [402]
R130  22,5%  [402]
R131  22,5%  [402]
R132  22,5%  [402]
R133  22,5%  [402]
R134  22,5%  [402]
R135  22,5%  [402]
R136  22,5%  [402]
R138  22,5%  [402]
R139  22,5%  [402]
R140  22,5%  [402]
R141  22,5%  [402]
R142  22,5%  [402]
R143  22,5%  [402]
R144  22,5%  [402]
R145  22,5%  [402]
R146  22,5%  [402]
R147  22,5%  [402]
R148  22,5%  [402]
R149  22,5%  [402]
R150  22,5%  [402]
R152  22,5%  [402]
R153  22,5%  [402]
R180  10K,1%  [402]
R181  10K,1%  [402]
R182  10K,1%  [402]
R183  10K,1%  [402]
R187  10K,1%  [402]
R188  10K,1%  [402]
R189  10K,1%  [402]
R190  10K,1%  [402]
R191  10K,1%  [402]
R192  10K,1%  [402]
R193  10K,1%  [402]
R194  10K,1%  [402]
R195  10K,1%  [402]
R196  10K,1%  [402]
R197  10K,1%  [402]
R239  10K,1%  [402]
R441  10K,1%,DNI  [402]
R442  0,1%  [402]
R443  0,1%  [402]
R444  0,1%  [402]
sheet P14 AM572x USB PORTS & HUB
C231  DNI  [402]
C235  18pF,50V  [402]
C236  470pF/201  [201]
C237  0.1uf  [402]
C238  10uF,6.3V  [603]
C239  0.1uf,16V  [402]
C240  18pF,50V  [402]
C241  0.1uf,16V  [402]
C242  0.1uf,16V  [402]
C243  470pF  [201]
C244  0.1uf,16V  [402]
C245  0.1uF  [402]
C246  2.2uF,6.3V  [402]
C479  1uF,50V  [1210]
C481  10uF,6.3V  [603]
C482  0.1uF/201  [201]
C483  0.1uF/201  [201]
C484  0.1uF/201  [201]
C485  0.1uF/201  [201]
C486  0.1uF/201  [201]
C487  0.1uF/201  [201]
C488  0.1uF/201  [201]
C489  0.1uF/201  [201]
C490  0.1uF/201  [201]
C491  0.1uF/201  [201]
C492  0.1uF/201  [201]
C493  0.1uF/201  [201]
C494  10uF,6.3V  [603]
D40  TPD2EUSB30ADR  [SOT3_DRT_1P0XP8MM]
D42  TPD1E10B06  [2XSON]
P7  Micro USB-B  [USB5_FCI-10103594]
R200  10K,1%,DNI  [402]
R201  1.87K,1%  [402]
R202  1M,1%  [402]
R203  4.99K,1%  [402]
R204  4.7K  [402]
R205  10K,1%  [402]
R206  8.25K,1%  [402]
R207  4.7K  [402]
R209  4.7K  [402]
R243  4.7K  [402]
R328  1K,5%,DNI  [402]
R329  16K  [402]
R330  90.9K,1%  [402]
R386  DNI  [402]
R393  0,DNI  [402]
R394  0,DNI  [402]
U16  TPS74801  [DRC10-11X33]
U17  TUSB8041  [VQFN64S9X9P5]
Y7  24MHz  [OSC4_87-146SMD_126X197-1]
sheet P16_AM572x, AUDIO, & DEBUG
C247  0.1uf,16V  [402]
C248  0.1uf,16V  [402]
C249  10uF,6.3V  [603]
C250  47uF,6.3V,1206  [1206]
C251  47uF,6.3V,1206  [1206]
C252  0.1uf,16V  [402]
C253  0.1uf,16V  [402]
C254  10uF,6.3V  [603]
C255  2.2uF,6.3V  [402]
C256  2.2uF,6.3V  [402]
C257  10uF,6.3V  [603]
C258  0.1uf,16V  [402]
C259  0.1uf,16V  [402]
C260  1uF,4V,0201  [201]
C261  4.7uF,6.3V  [402]
C262  0.1uf,16V  [402]
C263  0.1uf,16V  [402]
D8  PESD0603-240  [603]
D9  PESD0603-240  [603]
D10  PESD0603-240  [603]
D11  PESD0603-240  [603]
FB9  150OHM800mA  [805]
L12  FLT_HIFREQ_.47UF  [FLT3SMD_0805-2]
L13  BLM21PG221SN1D  [IND_0805]
L14  BLM21PG221SN1D  [IND_0805]
L15  BLM21PG221SN1D  [IND_0805]
P8  SJ1-3524NG  [JACK5-472X551-SJ1-3524NG]
P9  SJ1-3524NG  [JACK5-472X551-SJ1-3524NG]
P10  HEADER 6  [SIP6]
R223  22,5%  [402]
R224  10,5%  [402]
R225  10,5%  [402]
R226  20K,1%  [402]
R227  10,5%  [402]
R228  20K,1%  [402]
R229  10,5%  [402]
R230  10,5%  [402]
R231  20K,1%  [402]
R232  20K,1%  [402]
R233  10,5%  [402]
R234  20K,1%  [402]
R235  20K,1%  [402]
R236  100K,1%  [402]
U11  AM5728  [sktbga-zkk-6334-p760]  (sections -1,-10,-11,-12,-13,-14,-15,-16,-17,-18,-19,-2,-3,-4,-5,-6,-7,-8,-9)
U18  TLV320AIC3104  [QFN32]
U19  TPS77018DBV  [SOT23-5]
U20  SN74LVC2G241  [U_8_DCU]
sheet P17_AM572x_HDMI PORT
C264  0.1uf,16V  [402]
C265  4.7uF,6.3V  [402]
C441  47pF  [402]
C522  220pF  [402]
C523  0.1uf,16V  [402]
C524  220pF  [402]
C551  0,1%  [402]
C552  0,1%  [402]
C553  0,1%  [402]
C554  0,1%  [402]
C555  0,1%  [402]
C556  0,1%  [402]
C557  0,1%  [402]
C558  0,1%  [402]
D12  TPD1E05U06  [2XSON]
D13  TPD1E05U06  [2XSON]
D14  TPD1E05U06  [2XSON]
D15  TPD1E05U06  [2XSON]
D16  TPD1E05U06  [2XSON]
D17  TPD1E05U06  [2XSON]
D18  TPD1E05U06  [2XSON]
D19  TPD1E05U06  [2XSON]
FB12  BLM15BD182SN1  [402]
FB13  BLM15BD182SN1  [402]
FL1  DLW21SN900HQ2  [CHOKE4_0805-2]
FL2  DLW21SN900HQ2  [CHOKE4_0805-2]
FL3  DLW21SN900HQ2  [CHOKE4_0805-2]
FL4  DLW21SN900HQ2  [CHOKE4_0805-2]
P11  HDMI-RA-19-TYPEA  [hdmi-smt-w-flange]
R237  DNI,0402  [402]
R241  DNI,0402  [402]
R242  DNI,0402  [402]
R245  4.7K,DNI  [402]
R246  4.7K,DNI  [402]
R247  10K,1%,DNI  [402]
R248  10K,1%,DNI  [402]
R387  DNI  [402]
R445  DNI  [402]
R446  DNI  [402]
R447  DNI  [402]
R448  DNI  [402]
R449  DNI  [402]
R450  DNI  [402]
R451  DNI  [402]
R452  DNI  [402]
U21  TPD12S016 24UQFN  [QFN24S_2X4P4]
sheet P18_AM572x eMMC, MMC3 & uSD
C266  0.22uF/201  [201]
C267  2.2uF,6.3V  [402]
C268  4.7uF,6.3V  [402]
C269  0.22uF/201  [201]
C270  0.1uf,16V  [402]
C271  10uF,6.3V  [603]
C272  0.1uf,16V  [402]
C477  DNI  [402]
D20  TPD2E001DRL  [u_5_drl]
D21  TPD2E001DRL  [u_5_drl]
D22  TPD2E001DRL  [u_5_drl]
D23  TPD2E001DRL  [u_5_drl]
P12  SCHA5B0200  [SD-MICRO-SCHA5B0300]
R249  0,1%  [402]
R250  DNI,0402  [402]
R251  DNI,0402  [402]
R252  DNI,0402  [402]
R253  DNI,0402  [402]
R254  DNI,0402  [402]
R255  DNI,0402  [402]
R256  DNI,0402  [402]
R257  DNI,0402  [402]
R258  DNI,0402  [402]
R259  DNI,0402  [402]
R260  10K,1%  [402]
R261  10K,1%  [402]
R262  10K,1%  [402]
R263  10K,1%  [402]
R264  10K,1%  [402]
R265  10K,1%  [402]
R266  33,5%  [402]
R267  33,5%  [402]
R268  33,5%  [402]
R269  33,5%  [402]
R270  33,5%  [402]
R271  33,5%  [402]
R272  10K,1%  [402]
R406  DNI  [402]
U22  MEM_MNAND_4GB  [BGA153_P14_P5_11P5X13]
sheet P19_AM572x DDR INTERFACE 1
C273  0.1uF/201  [201]
R273  1K,5%  [402]
R274  1K,5%  [402]
R333  4.7K  [402]
sheet P20_AM572x DDR INTERFACE 2
C274  0.1uf,16V  [402]
R334  4.7K  [402]
sheet P21_DDR3  BANK 1
C275  0.22uF/201  [201]
C276  0.22uF/201  [201]
C277  0.22uF/201  [201]
C278  0.22uF/201  [201]
R275  240,1%  [402]
R276  240,1%  [402]
TP20  TP  [TP30C12D]
U23  256MBx16 DDR3L  [BGA96_T9_P8_9X14]
U24  256MBx16 DDR3L  [BGA96_T9_P8_9X14]

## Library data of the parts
C220 C229 C250 C251 = CAP_47uF_X5R_6.3V_20%_1206
C221 C261 C265 C268 = CAP_4.7uF_X5R_6.3V_20%_0402
C222 C224 C225 C228 C231 C239 C241 C242 C244 C247 C248 C252 C253 C258 C259 C262 C264 C270 C272 C274 C477 C523 C536-C538 C542 C543 = CAP_0.1uF_X7R_16V_10%_0402
C223 C226 C227 C234 C238 C249 C254 C257 C271 C479 C481 C494 = CAP_10uF_X5R_6.3V_20%_0603
C232 C233 = CAP_18PF_COG_50V_5%_0402
C539 C540 C544-C546 = CAP_6.8nF_X7R_50V_10%_0805
FB5 FB7-FB9 FB12 FB13 = FERRITE_180_800_0805
FB6 R111-R115 R118 R123 R249 R317 R393 R394 R442-R444 = RES_0_1_16W_1%_0402
Q2 = IRF5210S_SM_0
R99 R100 R116 R117 R273 R274 R328 = RES_1K_1_16W_5%_0402
R101-R104 R122 = RES_100K_1_16W_1%_0402
R105-R110 R124-R136 R138-R150 R152 R153 R223 = RES_22_1_16W_5%_0402
R119 = RES_12.1K_1_16W_1%_0402
R120 R180-R183 R187 R188 R190-R197 R200 R205 R236 R239 R247 R248 R260-R265 R272 R330 R441 = RES_10K_1_16W_1%_0402
R121 R189 R237 R241 R242 R250-R259 = RES_DNI_1_16W_1%_0402
R204 R207 R209 R243 R245 R246 R333 R334 R390 = RES_4.7K_1_16W_5%_0402
U15 = IC_KSZ9031RNX_QFN48_9
Y6 = CRYS_25MHz_18pF_2P_5.0x3.2
J3 J4 J6 = HDR_1x3_0.1
C235 C240 = CAP_33PF_COG_50V_5%_0402
C236 C243 C263 C273 C482-C493 = CAP_0.1uF_X5R_6.3V_20%_0201
C237 C245 = CAP_0.001_X7R_50V_10%_0402
C246 C255 C256 C267 = CAP_2.2uF_X5R_6.3V_10%_0402
D40 = IC_TPD2EUSB30ADRTR_1
D42 = IC_TPD1E05U06
P7 = CONN_MINI-USB-AB_1
R201 = RES_1.87K_1_16W_1%_0402
R202 R386 R387 R406 = RES_1M_1_16W_1%_0402
R203 = RES_4.99K_1_16W_1%_0402
R206 = RES_9.09K_1_16W_1%_0402
R226 R228 R231 R232 R234 R235 R329 = RES_20K_1_16W_1%_0402
U16 = PWR_TPS74801_SON
U17 = IC_TUSB8041_2
Y7 = CRYS_24MHz_2PIN
C260 = CAP_1.0UF_X5R_4V_20%_0201
D8-D11 = PROT_PESD0603_240
L12 = FLT_HIFREQ_.47UF
L13-L15 = FERRITE_220_0805
P8 P9 = CONN_STEREO_3.5MM_1SW
P10 = HEADER_6
R224 R225 R227 R229 R230 R233 = RES_10_1_10W_5%_0402
U11 = IC_AM572x_BGA_34
U18 = IC_TLV320AIC3104_5
U19 = PWR_TPS7018DBV_SOT23_5
U20 = IC_SN74LVC2G241_1
C441 = CAP_0.1uF_X7R_16V_10%_0402: Part Number: 04025A470JAT2A
C522 C524 C551-C558 = CAP: Part #: C0402C221K5RACTU
D12-D19 = IC_TPD1E05U06_0
FL1-FL4 = CHOKE_DLW21SN121HQ2_3
P11 = HDMI-RA-19_0
R275 R276 R445-R452 = RES_240_1_16W_1%_0402
U21 = IC_TPD12S016
C266 C269 C275-C278 = CAP_0.22uf_X5R_6.3V_20%_0201
D20-D23 = IC_TPD2E001DRL
P12 = microSD_CONN_0
R266-R271 = RES_33_1_16W_5%_0402
U22 = MEM_MNAND_1
TP20 = TP
U23 U24 = MEM_DDR3L_256MBx16_0

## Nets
5V0: FB13.1 ; also on sheet 2 4 26 27
GND: C220.2 C221.2 C222.1 C223.2 C224.1 C225.1 C226.2 C227.2 C228.1 C229.2 C231.1 C232.1 C233.1 C234.2 C235.2 C236.2 C237.2 C238.2 C240.2 C243.2 C245.2 C246.2 C252.2 C253.2 C254.2 C257.2 C258.2 C259.2 C260.2 C261.2 C262.2 C263.1 C264.2 C265.2 C266.2 C267.1 C268.2 C269.2 C270.1 C271.2 C272.1 C273.2 C274.1 C275.2 C276.2 C441.1 C477.1 C479.2 C481.2 C482.2 C483.2 C484.2 C485.2 C486.2 C487.2 C488.2 C489.2 C490.2 C491.2 C492.2 C493.2 C494.2 C522.2 C523.2 C524.2 C536.2 C537.2 C538.2 C539.2 C540.2 C542.2 C543.2 C544.2 C545.2 C546.2 D12.2(G) D13.2(G) D14.2(G) D15.2(G) D16.2(G) D17.2(G) D18.2(G) D19.2(G) D20.4(GND) D21.4(GND) D22.4(GND) D23.4(GND) D40.3(GND) D42.2(GND) FB9.1 J3.3 J4.3 J6.1 L12.2 P7.5(G1) P10.1 P11.2(D2_SHIELD) P11.5(D1_SHIELD) P11.8(D0_SHIELD) P11.11(CK_SHIELD) P11.17(GND) P12.6(VSS) P12.9(GND) R100.1 R116.2 R119.1 R180.2 R181.2 R183.2 R188.2 R190.2 R191.2 R192.2 R193.2 R194.2 R195.2 R200.1 R203.2 R205.2 R206.1 R207.1 R209.1 R231.2 R232.2 R236.2 R274.2 R275.2 R276.2 R328.2 R329.1 R333.2 R334.2 R386.1 R387.1 R406.1 R441.2 R442.2 R444.2 R445.2 R446.2 R447.2 R448.2 R449.2 R450.2 R451.2 R452.2 U11.AA11(VSSA_USB.2) U11.AB11(VSSA_USB.1) U11.AD10(VSSA_USB3) U11.AD19(VSSA_HDMI.2) U11.AE19(VSSA_HDMI.1) U15.29(VSS) U15.49(P_GND) U16.6(GND) U16.11(PAD) U17.65(PAD) U18.6(DVSS) U19.2(GND) U19.3(ENn) U20.1(~{1OE}) U20.4(GND) U21.5(GND1) U21.13(GND2) U21.18(GND3) U22.C4(VSSQ4) U22.E7(VSS2) U22.G5(VSS1) U22.H10(VSS3) U22.K8(VSS4) U22.N2(VSSQ1) U22.N5(VSS5) U22.P4(VSSQ3) U22.P6(VSSQ2) U23.A9(VSS.1) U23.B1(VSSQ.1) U23.B3(VSS.2) U23.B9(VSSQ.2) U23.D1(VSSQ.3) U23.D8(VSSQ.4) U23.E1(VSS.3) U23.E2(VSSQ.5) U23.E8(VSSQ.6) U23.F9(VSSQ.7) U23.G1(VSSQ.8) U23.G8(VSS.4) U23.G9(VSSQ.9) U23.J2(VSSDL) U23.J8(VSS.5) U23.M1(VSS.6) U23.M9(VSS.7) U23.P1(VSS.8) U23.P9(VSS.9) U23.T1(VSS.10) U23.T9(VSS.11) U24.A9(VSS.1) U24.B1(VSSQ.1) U24.B3(VSS.2) U24.B9(VSSQ.2) U24.D1(VSSQ.3) U24.D8(VSSQ.4) U24.E1(VSS.3) U24.E2(VSSQ.5) U24.E8(VSSQ.6) U24.F9(VSSQ.7) U24.G1(VSSQ.8) U24.G8(VSS.4) U24.G9(VSSQ.9) U24.J2(VSSDL) U24.J8(VSS.5) U24.M1(VSS.6) U24.M9(VSS.7) U24.P1(VSS.8) U24.P9(VSS.9) U24.T1(VSS.10) U24.T9(VSS.11) ; also on sheet 2 3 4 5 6 7 8 9 10 11 21 22 23 24 25 26 27
GND_EARTH: C231.2 C441.2 C477.2 D8.1 D9.1 D10.1 D11.1 P7.S1(G2) P7.S2(G3) P7.S3(G4) P7.S4(G5) P11.MTG3 P11.MTG4 P12.13(GND5) P12.14(GND6) R386.2 R387.2 R406.2 ; also on sheet 2 3 8 11 24
GND_SIGNAL: C247.2 C248.2 C249.2 FB9.2 P8.1 P9.1 R226.2 R228.2 R234.2 R235.2 U18.17(AVSS_ADC) U18.21(DRVSS) U18.26(AVSS_DAC) U18.33(PAD)
VBUS_DET: U11.B11(GPIO4_21) ; also on sheet 3
VDD_1.1: C481.1 C482.1 C483.1 C484.1 C485.1 C486.1 C487.1 C488.1 C489.1 R201.1 U16.9(OUTB) U16.10(OUTA) U17.5(VDD1) U17.8(VDD2) U17.13(VDD3) U17.21(VDD4) U17.28(VDD5) U17.31(VDD6) U17.51(VDD7) U17.57(VDD8)
VDD_3V3: C263.2 C268.1 C269.1 C271.1 C272.2 C490.1 C491.1 C492.1 C493.1 C494.1 FB7.1 FB12.1 J3.1 J4.1 J6.3 L12.1 P12.4(VDD) R189.2 R196.2 R197.2 R204.2 R243.1 R249.2 R390.1 R443.2 U16.1(INA) U16.2(INB) U16.4(BIAS) U16.5(EN) U17.16(VDD33_1) U17.34(VDD33_2) U17.52(VDD33_3) U17.63(VDD33_4) U20.7(2OE) U20.8(VCC) U22.C6(VCCQ4) U22.M4(VCCQ5) U22.N4(VCCQ3) U22.P5(VCCQ2) ; also on sheet 2 3 4 6 7 8 9 10 11 23 24 25 26 27
VDD_DDR: C277.2 C278.2 R273.1 U23.A1(VDDQ.1) U23.A8(VDDQ.2) U23.B2(VDD.1) U23.C1(VDDQ.3) U23.C9(VDDQ.4) U23.D2(VDDQ.5) U23.D9(VDD.2) U23.E9(VDDQ.6) U23.F1(VDDQ.7) U23.G7(VDD.3) U23.H2(VDDQ.8) U23.H9(VDDQ.9) U23.K2(VDDL) U23.K8(VDD.4) U23.N1(VDD.5) U23.N9(VDD.6) U23.R1(VDD.7) U23.R9(VDD.8) U24.A1(VDDQ.1) U24.A8(VDDQ.2) U24.B2(VDD.1) U24.C1(VDDQ.3) U24.C9(VDDQ.4) U24.D2(VDDQ.5) U24.D9(VDD.2) U24.E9(VDDQ.6) U24.F1(VDDQ.7) U24.G7(VDD.3) U24.H2(VDDQ.8) U24.H9(VDDQ.9) U24.K2(VDDL) U24.K8(VDD.4) U24.N1(VDD.5) U24.N9(VDD.6) U24.R1(VDD.7) U24.R9(VDD.8) ; also on sheet 5 10 21 22 23
VDD_SD: D20.1(VCC) D21.1(VCC) D22.1(VCC) D23.1(VCC) R260.1 R261.1 R262.1 R263.1 R264.1 R265.1 R272.1 ; also on sheet 4 9
VDDA_1V8_PHYA: C243.1 C245.1 U11.AA13(VDDA_USB1) U11.AB12(VDDA_USB2) ; also on sheet 4 10
VIN3A_CLKO: U11.P1(VIN3X_CLKO) ; also on sheet 26
VIN3A_D0: R239.1 U11.M6(VIN3A_D0) ; also on sheet 26
VIN3A_D1: R189.1 U11.M2(VIN3A_D1) ; also on sheet 26
VIN3A_D2: R183.1 U11.L5(VIN3A_D2) ; also on sheet 26
VIN3A_D3: R188.1 U11.M1(VIN3A_D3) ; also on sheet 26
VIN3A_D4: R182.1 U11.L6(VIN3A_D4) ; also on sheet 26
VIN3A_D5: R187.1 U11.L4(VIN3A_D5) ; also on sheet 26
VIN3A_D6: R181.1 U11.L3(VIN3A_D6) ; also on sheet 26
VIN3A_D7: R180.1 U11.L2(VIN3A_D7) ; also on sheet 26
VIN3A_D8: R196.1 U11.L1(VIN3A_D8) ; also on sheet 26
VIN3A_D9: R195.1 U11.K2(VIN3A_D9) ; also on sheet 26
VIN3A_D10: R194.1 U11.J1(VIN3A_D10) ; also on sheet 26
VIN3A_D11: R193.1 U11.J2(VIN3A_D11) ; also on sheet 26
VIN3A_D12: R192.1 U11.H1(VIN3A_D12) ; also on sheet 26
VIN3A_D13: R191.1 U11.J3(VIN3A_D13) ; also on sheet 26
VIN3A_D14: R190.1 U11.H2(VIN3A_D14) ; also on sheet 26
VIN3A_D15: R197.1 R441.1 U11.H3(VIN3A_D15) ; also on sheet 26
VIN3A_D16: U11.R6(VIN3A_D16) ; also on sheet 26
VIN3A_D17: U11.T9(VIN3A_D17) ; also on sheet 26
VIN3A_D18: U11.T6(VIN3A_D18) ; also on sheet 26
VIN3A_D19: U11.T7(VIN3A_D19) ; also on sheet 26
VIN3A_D20: U11.P6(VIN3A_D20) ; also on sheet 26
VIN3A_D21: U11.R9(VIN3A_D21) ; also on sheet 26
VIN3A_D22: U11.R5(VIN3A_D22) ; also on sheet 26
VIN3A_D23: U11.P5(VIN3A_D23) ; also on sheet 26
VIN3A_DEO: U11.N9(VIN3A_DEO) ; also on sheet 26
VIN3A_FLD: U11.P9(VIN3A_FLD) ; also on sheet 26
VIN3A_HSYNC: U11.N7(VIN3A_HSYNC) ; also on sheet 26
VIN3A_VSYNC: U11.R4(VIN3A_VSYNC) ; also on sheet 26
74801SS: R200.2 U16.7(SS)
AIC_AVDD_DAC3.3: C248.1 C249.1 L13.2 U18.25(AVDD_DAC)
AIC_BCLK: R227.2 R231.1 U18.2(BCLK)
AIC_BCLKR: R227.1 U11.B18(MCASP3_ACLKX)
AIC_DIN: R225.2 R232.1 U18.4(DIN)
AIC_DINR: R225.1 U11.B19(MCASP3_AXR0)
AIC_DOUT: R229.2 U18.5(DOUT)
AIC_DOUTR: R229.1 U11.C17(MCASP3_AXR1)
AIC_DRVDD3.3: C257.1 C258.1 C259.1 L15.2 U18.18(DRVDD) U18.24(DRVDD)
AIC_DVDD: C261.1 C262.1 U18.32(DVDD) U19.5(OUT)
AIC_IOVDD3.3: C253.1 C254.1 L14.2 U18.7(IOVDD)
AIC_MCLK: R223.2 U18.1(MCLK)
AIC_MCLKR: R223.1 U11.D18(CLKOOUT2)
AIC_WCLK: R224.2 U18.3(WCLK)
AIC_WCLKR: R224.1 U11.F15(MCASP3_FSX)
AUDIN_L: R230.1 U18.14(IN2L)
AUDIN_R: R233.1 U18.16(IN2R)
AUDIN_RL: C256.1 R233.2
AUDIN_RR: C255.1 R230.2
AUDIO_L: C250.1 U18.27(LEFT_LOP)
AUDIO_R: C251.1 U18.29(RIGHT_LOP)
B_UART3_RX: P10.4 R236.1 U20.2(1A)
B_UART3_TX: P10.5 U20.3(2Y)
BATEN0: R204.1 U17.36(PWRON1Z_BATEN1) ; also on sheet 24
BATEN1: U17.35(PWRON2Z_BATEN2) ; also on sheet 24
BATEN2: U17.33(PWRON3Z_BATEN3) ; also on sheet 24
BATEN3: U17.32(PWRON4Z_BATEN4) ; also on sheet 24
CLKOUT3: U11.C23(CLKOUT3) ; also on sheet 26
CON_MMC1_CLK: D21.3(IO1) P12.5(CLOCK) R262.2 R269.2
CON_MMC1_CMD: D21.5(IO2) P12.3(CMD) R263.2 R267.2
CON_MMC1_DAT0: D20.5(IO2) P12.7(DAT0) R261.2 R270.2
CON_MMC1_DAT1: D20.3(IO1) P12.8(DAT1) R260.2 R271.2
CON_MMC1_DAT2: D22.5(IO2) P12.1(DAT2) R265.2 R266.2
CON_MMC1_DAT3: D22.3(IO1) P12.2(CD/DAT3) R264.2 R268.2
DDR1_A0: U11.AD20(DDR1_A0) U23.N3(A0) U24.N3(A0) ; also on sheet 23
DDR1_A1: U11.AC19(DDR1_A1) U23.P7(A1) U24.P7(A1) ; also on sheet 23
DDR1_A2: U11.AC20(DDR1_A2) U23.P3(A2) U24.P3(A2) ; also on sheet 23
DDR1_A3: U11.AB19(DDR1_A3) U23.N2(A3) U24.N2(A3) ; also on sheet 23
DDR1_A4: U11.AF21(DDR1_A4) U23.P8(A4) U24.P8(A4) ; also on sheet 23
DDR1_A5: U11.AH22(DDR1_A5) U23.P2(A5) U24.P2(A5) ; also on sheet 23
DDR1_A6: U11.AG23(DDR1_A6) U23.R8(A6) U24.R8(A6) ; also on sheet 23
DDR1_A7: U11.AE21(DDR1_A7) U23.R2(A7) U24.R2(A7) ; also on sheet 23
DDR1_A8: U11.AF22(DDR1_A8) U23.T8(A8) U24.T8(A8) ; also on sheet 23
DDR1_A9: U11.AE22(DDR1_A9) U23.R3(A9) U24.R3(A9) ; also on sheet 23
DDR1_A10: U11.AD21(DDR1_A10) U23.L7(A10) U24.L7(A10) ; also on sheet 23
DDR1_A11: U11.AD22(DDR1_A11) U23.R7(A11) U24.R7(A11) ; also on sheet 23
DDR1_A12: U11.AC21(DDR1_A12) U23.N7(A12) U24.N7(A12) ; also on sheet 23
DDR1_A13: U11.AF18(DDR1_A13) U23.T3(A13) U24.T3(A13) ; also on sheet 23
DDR1_A14: U11.AE17(DDR1_A14) U23.T7(A14) U24.T7(A14) ; also on sheet 23
DDR1_A15: U11.AD18(DDR1_A15) U23.M7(NC.M7/A15) U24.M7(NC.M7/A15) ; also on sheet 23
DDR1_BA0: U11.AF17(DDR1_BA0) U23.M2(BA0) U24.M2(BA0) ; also on sheet 23
DDR1_BA1: U11.AE18(DDR1_BA1) U23.N8(BA1) U24.N8(BA1) ; also on sheet 23
DDR1_BA2: U11.AB18(DDR1_BA2) U23.M3(BA2) U24.M3(BA2) ; also on sheet 23
DDR1_CASN: U11.AC18(DDR1_CASN) U23.K3(CAS#) U24.K3(CAS#) ; also on sheet 23
DDR1_CKE: R333.1 U11.AG22(DDR1_CKE) U23.K9(CKE) U24.K9(CKE) ; also on sheet 23
DDR1_CLK0: U11.AG24(DDR1_CK) U23.J7(CK) U24.J7(CK) ; also on sheet 23
DDR1_CLK0N: U11.AH24(DDR1_NCK) U23.K7(CK#) U24.K7(CK#) ; also on sheet 23
DDR1_CSN0: U11.AH23(DDR1_CS0N) U23.L2(CS#) U24.L2(CS#) ; also on sheet 23
DDR1_D0: U11.AF25(DDR1_D0) U23.E3(DQ0)
DDR1_D1: U11.AF26(DDR1_D1) U23.H3(DQ4)
DDR1_D2: U11.AG26(DDR1_D2) U23.F8(DQ3)
DDR1_D3: U11.AH26(DDR1_D3) U23.F7(DQ1)
DDR1_D4: U11.AF24(DDR1_D4) U23.G2(DQ6)
DDR1_D5: U11.AE24(DDR1_D5) U23.H7(DQ7)
DDR1_D6: U11.AF23(DDR1_D6) U23.F2(DQ2)
DDR1_D7: U11.AE23(DDR1_D7) U23.H8(DQ5)
DDR1_D8: U11.AC23(DDR1_D8) U23.D7(DQ8)
DDR1_D9: U11.AF27(DDR1_D9) U23.C3(DQ9)
DDR1_D10: U11.AG27(DDR1_D10) U23.A3(DQ15)
DDR1_D11: U11.AF28(DDR1_D11) U23.C8(DQ10)
DDR1_D12: U11.AE26(DDR1_D12) U23.B8(DQ14)
DDR1_D13: U11.AC25(DDR1_D13) U23.A2(DQ13)
DDR1_D14: U11.AC24(DDR1_D14) U23.C2(DQ11)
DDR1_D15: U11.AD25(DDR1_D15) U23.A7(DQ12)
DDR1_D16: U11.V20(DDR1_D16) U24.E3(DQ0)
DDR1_D17: U11.W20(DDR1_D17) U24.H8(DQ5)
DDR1_D18: U11.AB28(DDR1_D18) U24.F8(DQ3)
DDR1_D19: U11.AC28(DDR1_D19) U24.H7(DQ7)
DDR1_D20: U11.AC27(DDR1_D20) U24.H3(DQ4)
DDR1_D21: U11.Y19(DDR1_D21) U24.G2(DQ6)
DDR1_D22: U11.AB27(DDR1_D22) U24.F7(DQ1)
DDR1_D23: U11.Y20(DDR1_D23) U24.F2(DQ2)
DDR1_D24: U11.AA23(DDR1_D24) U24.D7(DQ8)
DDR1_D25: U11.Y22(DDR1_D25) U24.C3(DQ9)
DDR1_D26: U11.Y23(DDR1_D26) U24.A3(DQ15)
DDR1_D27: U11.AA24(DDR1_D27) U24.B8(DQ14)
DDR1_D28: U11.Y24(DDR1_D28) U24.A7(DQ12)
DDR1_D29: U11.AA26(DDR1_D29) U24.C8(DQ10)
DDR1_D30: U11.AA25(DDR1_D30) U24.A2(DQ13)
DDR1_D31: U11.AA28(DDR1_D31) U24.C2(DQ11)
DDR1_DQM0: U11.AD23(DDR1_DQM0) U23.E7(LDM)
DDR1_DQM1: U11.AB23(DDR1_DQM1) U23.D3(UDM)
DDR1_DQM2: U11.AC26(DDR1_DQM2) U24.E7(LDM)
DDR1_DQM3: U11.AA27(DDR1_DQM3) U24.D3(UDM)
DDR1_DQS0: U11.AH25(DDR1_DQS0) U23.F3(LDQS)
DDR1_DQS1: U11.AE27(DDR1_DQS1) U23.C7(UDQS)
DDR1_DQS2: U11.AD27(DDR1_DQS2) U24.F3(LDQS)
DDR1_DQS3: U11.Y28(DDR1_DQS3) U24.C7(UDQS)
DDR1_DQS_ECC: R274.1 U11.V27(DDR1_DQS_ECC)
DDR1_DQSN0: U11.AG25(DDR1_DQSN0) U23.G3(LDQS#)
DDR1_DQSN1: U11.AE28(DDR1_DQSN1) U23.B7(UDQS#)
DDR1_DQSN2: U11.AD28(DDR1_DQSN2) U24.G3(LDQS#)
DDR1_DQSN3: U11.Y27(DDR1_DQSN3) U24.B7(UDQS#)
DDR1_DQSN_ECC: R273.2 U11.V28(DDR1_DQSN_ECC)
DDR1_ODT0: U11.AE20(DDR1_ODT0) U23.K1(ODT) U24.K1(ODT) ; also on sheet 23
DDR1_RASN: U11.AF20(DDR1_RASN) U23.J3(RAS#) U24.J3(RAS#) ; also on sheet 23
DDR1_RST: TP20.1 U11.AG21(DDR1_RST) U23.T2(RSTn) U24.T2(RSTn)
DDR1_WEN: U11.AH21(DDR1_WEN) U23.L3(WE#) U24.L3(WE#) ; also on sheet 23
DDR2_A0: U11.R25(DDR2_A0) ; also on sheet 21 22
DDR2_A1: U11.R26(DDR2_A1) ; also on sheet 21 22
DDR2_A2: U11.R28(DDR2_A2) ; also on sheet 21 22
DDR2_A3: U11.R27(DDR2_A3) ; also on sheet 21 22
DDR2_A4: U11.P23(DDR2_A4) ; also on sheet 21 22
DDR2_A5: U11.P22(DDR2_A5) ; also on sheet 21 22
DDR2_A6: U11.P25(DDR2_A6) ; also on sheet 21 22
DDR2_A7: U11.N20(DDR2_A7) ; also on sheet 21 22
DDR2_A8: U11.P27(DDR2_A8) ; also on sheet 21 22
DDR2_A9: U11.N27(DDR2_A9) ; also on sheet 21 22
DDR2_A10: U11.N23(DDR2_A10) ; also on sheet 21 22
DDR2_A11: U11.P26(DDR2_A11) ; also on sheet 21 22
DDR2_A12: U11.N28(DDR2_A12) ; also on sheet 21 22
DDR2_A13: U11.T22(DDR2_A13) ; also on sheet 21 22
DDR2_A14: U11.R22(DDR2_A14) ; also on sheet 21 22
DDR2_A15: U11.U22(DDR2_A15) ; also on sheet 21 22
DDR2_BA0: U11.U23(DDR2_BA0) ; also on sheet 21 22
DDR2_BA1: U11.U27(DDR2_BA1) ; also on sheet 21 22
DDR2_BA2: U11.U26(DDR2_BA2) ; also on sheet 21 22
DDR2_CASN: U11.U28(DDR2_CASN) ; also on sheet 21 22
DDR2_CKE: R334.1 U11.U24(DDR2_CKE) ; also on sheet 21 22
DDR2_CLK0: U11.T28(DDR2_CK) ; also on sheet 21 22
DDR2_CLK0N: U11.T27(DDR2_NCK) ; also on sheet 21 22
DDR2_CSN0: U11.P24(DDR2_CSN0) ; also on sheet 21 22
DDR2_D0: U11.E26(DDR2_D0) ; also on sheet 21
DDR2_D1: U11.G25(DDR2_D1) ; also on sheet 21
DDR2_D2: U11.F25(DDR2_D2) ; also on sheet 21
DDR2_D3: U11.F24(DDR2_D3) ; also on sheet 21
DDR2_D4: U11.F26(DDR2_D4) ; also on sheet 21
DDR2_D5: U11.F27(DDR2_D5) ; also on sheet 21
DDR2_D6: U11.E27(DDR2_D6) ; also on sheet 21
DDR2_D7: U11.E28(DDR2_D7) ; also on sheet 21
DDR2_D8: U11.H23(DDR2_D8) ; also on sheet 21
DDR2_D9: U11.H25(DDR2_D9) ; also on sheet 21
DDR2_D10: U11.H24(DDR2_D10) ; also on sheet 21
DDR2_D11: U11.H26(DDR2_D11) ; also on sheet 21
DDR2_D12: U11.G26(DDR2_D12) ; also on sheet 21
DDR2_D13: U11.J25(DDR2_D13) ; also on sheet 21
DDR2_D14: U11.J26(DDR2_D14) ; also on sheet 21
DDR2_D15: U11.J24(DDR2_D15) ; also on sheet 21
DDR2_D16: U11.L22(DDR2_D16) ; also on sheet 21
DDR2_D17: U11.K20(DDR2_D17) ; also on sheet 21
DDR2_D18: U11.K21(DDR2_D18) ; also on sheet 21
DDR2_D19: U11.L23(DDR2_D19) ; also on sheet 21
DDR2_D20: U11.L24(DDR2_D20) ; also on sheet 21
DDR2_D21: U11.J23(DDR2_D21) ; also on sheet 21
DDR2_D22: U11.K22(DDR2_D22) ; also on sheet 21
DDR2_D23: U11.J20(DDR2_D23) ; also on sheet 21
DDR2_D24: U11.L27(DDR2_D24) ; also on sheet 21
DDR2_D25: U11.L26(DDR2_D25) ; also on sheet 21
DDR2_D26: U11.L25(DDR2_D26) ; also on sheet 21
DDR2_D27: U11.L28(DDR2_D27) ; also on sheet 21
DDR2_D28: U11.M23(DDR2_D28) ; also on sheet 21
DDR2_D29: U11.M24(DDR2_D29) ; also on sheet 21
DDR2_D30: U11.M25(DDR2_D30) ; also on sheet 21
DDR2_D31: U11.M26(DDR2_D31) ; also on sheet 21
DDR2_DQM0: U11.F28(DDR2_DQM0) ; also on sheet 21
DDR2_DQM1: U11.G24(DDR2_DQM1) ; also on sheet 21
DDR2_DQM2: U11.K23(DDR2_DQM2) ; also on sheet 21
DDR2_DQM3: U11.M22(DDR2_DQM3) ; also on sheet 21
DDR2_DQS0: U11.G28(DDR2_DQS0) ; also on sheet 21
DDR2_DQS1: U11.H27(DDR2_DQS1) ; also on sheet 21
DDR2_DQS2: U11.K27(DDR2_DQS2) ; also on sheet 21
DDR2_DQS3: U11.M28(DDR2_DQS3) ; also on sheet 21
DDR2_DQSN0: U11.G27(DDR2_DQSn0) ; also on sheet 21
DDR2_DQSN1: U11.H28(DDR2_DQSN1) ; also on sheet 21
DDR2_DQSN2: U11.K28(DDR2_DQSN2) ; also on sheet 21
DDR2_DQSN3: U11.M27(DDR2_DQSN3) ; also on sheet 21
DDR2_ODT0: U11.R23(DDR2_ODT0) ; also on sheet 21 22
DDR2_RASN: U11.T23(DDR2_RASN) ; also on sheet 21 22
DDR2_RST: U11.R24(DDR2_RST) ; also on sheet 21
DDR2_WEN: U11.U25(DDR2_WEN) ; also on sheet 21 22
DDR_VREF_OFFn: U11.A22(GPIO7_11) ; also on sheet 23
DDR_VREFSTL1: C273.1 C275.1 C276.1 C277.1 C278.1 U11.Y18(DDR1_VREF0) U23.H1(VREFDQ) U23.M8(VREFCA) U24.H1(VREFDQ) U24.M8(VREFCA) ; also on sheet 23
DDR_VREFSTL2: C274.2 U11.N22(DDR2_VREF0) ; also on sheet 21 23
DMA_EVT1: U11.P7(DMA_EVT1) ; also on sheet 26
DMA_EVT3: U11.N6(DMA_EVT3) ; also on sheet 26
DMA_EVT4: U11.M4(DMA_EVT4) ; also on sheet 26
E1_AVDDL: C225.2 C226.1 FB6.2 U15.4(AVDDL2) U15.9(AVDDL1)
E1_DVDDL: C227.1 C228.2 C542.1 C543.1 C544.1 C545.1 C546.1 FB8.2 U15.14(DVDDL1) U15.18(DVDDL5) U15.23(DVDDL4) U15.26(DVDDL6) U15.30(DVDDL2) U15.39(DVDDL3)
E1_GRN: R116.1 U15.17(LED1_/_PME_N1) ; also on sheet 11
E1_ISET: R119.2 U15.48(ISET)
E1_PLL: C223.1 C224.2 FB5.2 U15.44(AVDDL_PLL)
E1_RSTN: C234.1 R122.2 R123.2 R317.2 U15.42(RESET_N)
E1_XI: C232.2 R121.2 U15.46(XI) Y6.2(NC0)
E1_XO: C233.2 R121.1 U15.45(XO) Y6.1
E1_YEL: R117.1 U15.15(LED2) ; also on sheet 11
EMAC(1)_RXD0: R107.1 U11.A4(EMAC(1)_RXD0)
EMAC(1)_RXD1: R108.1 U11.B5(EMAC(1)_RXD1)
EMAC(1)_RXD2: R109.1 U11.B4(EMAC(1)_RXD2)
EMAC(1)_RXD3: R110.1 U11.B3(EMAC(1)_RXD3)
EMAC[1]_RXC: R106.1 U11.C5(EMAC(1)_RXC)
EMAC[1]_RXCTL: R105.1 U11.A3(EMAC(1)_RXCTL)
EMAC[1]_TXC: R112.1 U11.D5(EMAC(1)_TXC)
EMAC[1]_TXCTL: R111.1 U11.C2(EMAC(1)_TXCTL)
EMAC[1]_TXD0: R113.1 U11.D6(EMAC(1)_TXD0)
EMAC[1]_TXD1: R114.1 U11.B2(EMAC(1)_TXD1)
EMAC[1]_TXD2: R115.1 U11.C4(EMAC(1)_TXD2)
EMAC[1]_TXD3: R118.1 U11.C3(EMAC(1)_TXD3)
EMMC_VDD1.1: C270.2 U22.C2(VCCI)
ENET1_INTn: R390.2 U15.38(INT_N_/_PME_N2) ; also on sheet 27
ENET_PORZ: R123.1 ; also on sheet 8 11
ETH1_1.2V: C221.1 C222.2 FB5.1 FB6.1 FB8.1 Q2.2(D1) Q2.4(D2)
ETH1_3V3: C220.1 C229.1 C536.1 C537.1 C538.1 C539.1 C540.1 FB7.2 Q2.3(S) R99.1 R101.1 R102.1 R103.1 R104.1 R117.2 R120.2 R122.1 U15.1(AVDDH1) U15.12(AVDDH2) U15.16(DVDDH5) U15.34(DVDDH3) U15.40(DVDDH4)
ETH1_LDO: Q2.1(G) U15.43(LDO_O)
ETH_RESETn: R317.1 ; also on sheet 11
GPIO2_2: U11.P4(GPIO2_2) ; also on sheet 26
GPIO2_3: U11.R3(GPIO2_3) ; also on sheet 26
GPIO2_4: U11.T2(GPIO2_4) ; also on sheet 26
GPIO2_5: U11.U2(GPIO2_5) ; also on sheet 26
GPIO2_6: U11.U1(GPIO2_6) ; also on sheet 26
GPIO2_8: U11.R2(GPIO2_8) ; also on sheet 26
GPIO2_17: U11.P3(GPIO2_17) ; also on sheet 26
GPIO2_19: U11.T1(GPIO2_19) ; also on sheet 26
GPIO2_20: U11.P2(GPIO2_20) ; also on sheet 26
GPIO2_23: U11.N1(GPIO2_23) ; also on sheet 26
GPIO2_24: U11.M5(GPIO2_24) ; also on sheet 26
GPIO2_25: U11.M3(GPIO2_25) ; also on sheet 26
GPIO2_28: U11.N2(GPIO2_28) ; also on sheet 26
GPIO5_4: U11.G13(GPIO5_4) ; also on sheet 26
GPIO5_5: U11.J11(GPIO5_5) ; also on sheet 26
GPIO5_6: U11.E12(GPIO5_6) ; also on sheet 26
GPIO5_7: U11.F13(GPIO5_7) ; also on sheet 26
GPIO5_8: U11.C12(GPIO5_8) ; also on sheet 26
GPIO5_9: U11.D12(GPIO5_9) ; also on sheet 26
GPIO6_19: U11.B26(GPIO6_19) ; also on sheet 26
GRSTz: C246.1 U17.50(GRSTz)
HDMI1_DDC_SCL: R246.2 U11.C25(HDMI1_DDC_SCL) U21.1(SCL_A)
HDMI1_DDC_SDA: R245.2 U11.F17(HDMI1_DDC_SDA) U21.2(SDA_A)
HDMI_5VOUT: C265.1 C522.1 P11.18(+5V) R241.1 R242.1 U21.12(5V_OUT)
HDMI_CEC_A: U11.B20(HDMI_CEC) U21.24(CEC_A)
HDMI_CEC_B: P11.13(CE_REMOTE) R237.2 U21.6(CEC_B)
HDMI_CT_HPD: R248.1 U11.A24(GPIO7_10) U21.11(CT_HPD)
HDMI_HPD_A: U11.B21(HDMI_HPD) U21.3(HPD_A)
HDMI_HPD_B: P11.19(HP_DET) U21.9(HPD_B)
HDMI_LS_OE: R247.1 U11.AG8(GPIO2_30) U21.4(LS_OE)
HDMI_SCL_B: P11.15(DDC_CLK) R241.2 U21.7(SCL_B)
HDMI_SDA_B: P11.16(DDC_DATA) R242.2 U21.8(SDA_B)
HDMI_TX0+: D16.1(I) FL3.3 P11.7(D0+)
HDMI_TX0-: D17.1(I) FL3.2 P11.9(D0-)
HDMI_TX1+: D14.1(I) FL2.3 P11.4(D1+)
HDMI_TX1-: D15.1(I) FL2.2 P11.6(D1-)
HDMI_TX2+: D12.1(I) FL1.3 P11.1(D2+)
HDMI_TX2-: D13.1(I) FL1.2 P11.3(D2-)
HDMI_TXC+: D18.1(I) FL4.3 P11.10(CK+)
HDMI_TXC-: D19.1(I) FL4.2 P11.12(CK-)
HUB_XI: C235.1 R202.1 U17.62(XI) Y7.1
HUB_XO: C240.1 R202.2 U17.61(XO) Y7.2
I2C1_SCL: U18.8(SCL) ; also on sheet 2 3 7 27
I2C1_SDA: U18.9(SDA) ; also on sheet 2 3 7 27
I2C3_SCL: R393.1 ; also on sheet 4 27
I2C3_SDA: R394.1 ; also on sheet 4 27
I2C4_SCL: U11.J14(I2C4_SCL) ; also on sheet 26
I2C4_SDA: U11.B14(I2C4_SDA) ; also on sheet 26
LEFT_IN: C255.2 D10.2 P9.2 R235.1
LEFT_OUT: C250.2 D8.2 P8.2 R226.1
MCASP2_ACLKR: U11.E15(MCASP2_ACLKR) ; also on sheet 26
MCASP2_AXR0: U11.B15(MCASP2_AXR0) ; also on sheet 26
MCASP2_AXR1: U11.A15(MCASP2_AXR1) ; also on sheet 26
MCASP2_AXR4: U11.D15(MCASP2_AXR4) ; also on sheet 26
MCASP2_AXR5: U11.B16(MCASP2_AXR5) ; also on sheet 26
MCASP2_AXR6: U11.B17(MCASP2_AXR6) ; also on sheet 26
MCASP2_AXR7: U11.A17(MCASP2_AXR7) ; also on sheet 26
MCASP2_FSR: U11.A20(MCASP2_FSR) ; also on sheet 26
MDIO_CLK: U15.36(MDC) ; also on sheet 11
MDIO_DATA: U15.37(MDIO) ; also on sheet 11
MMC1_CLK: R269.1 U11.W6(MMC1_CLK)
MMC1_CMD: R267.1 U11.Y6(MMC1_CMD)
MMC1_DAT0: R270.1 U11.AA6(MMC1_DAT0)
MMC1_DAT1: R271.1 U11.Y4(MMC1_DAT1)
MMC1_DAT2: R266.1 U11.AA5(MMC1_DAT2)
MMC1_DAT3: R268.1 U11.Y3(MMC1_DAT3)
MMC1_SD_CD: D23.5(IO2) P12.10(CD) R272.2 U11.W7(MMC1_SDCD)
MMC2_3V3: C266.1 C267.2 R249.1 R250.2 R251.2 R252.2 R253.2 R254.2 R255.2 R256.2 R257.2 R258.2 R259.2 U22.E6(VCC3) U22.F5(VCC2) U22.J10(VCC0) U22.K9(VCC1) U22.P3(VCCQ1)
MMC2_CLK: R250.1 U11.J7(MMC2_CLK) U22.M6(CLK)
MMC2_CMD: R251.1 U11.H6(MMC2_CMD) U22.M5(CMD)
MMC2_DAT0: R252.1 U11.J4(MMC2_DAT0) U22.A3(DAT0)
MMC2_DAT1: R253.1 U11.J6(MMC2_DAT1) U22.A4(DAT1)
MMC2_DAT2: R254.1 U11.H4(MMC2_DAT2) U22.A5(DAT2)
MMC2_DAT3: R255.1 U11.H5(MMC2_DAT3) U22.B2(DAT3)
MMC2_DAT4: R256.1 U11.K7(MMC2_DAT4) U22.B3(DAT4)
MMC2_DAT5: R257.1 U11.M7(MMC2_DAT5) U22.B4(DAT5)
MMC2_DAT6: R258.1 U11.J5(MMC2_DAT6) U22.B5(DAT6)
MMC2_DAT7: R259.1 U11.K6(MMC2_DAT7) U22.B6(DAT7)
MMC3_CLK: U11.AD4(MMC3_CLK) ; also on sheet 26
MMC3_CMD: U11.AC4(MMC3_CMD) ; also on sheet 26
MMC3_DAT0: U11.AC7(MMC3_DAT0) ; also on sheet 26
MMC3_DAT1: U11.AC6(MMC3_DAT1) ; also on sheet 26
MMC3_DAT2: U11.AC9(MMC3_DAT2) ; also on sheet 26
MMC3_DAT3: U11.AC3(MMC3_DAT3) ; also on sheet 26
MMC3_DAT4: U11.AC8(MMC3_DAT4) ; also on sheet 26
MMC3_DAT5: U11.AD6(MMC3_DAT5) ; also on sheet 26
MMC3_DAT6: U11.AB8(MMC3_DAT6) ; also on sheet 26
MMC3_DAT7: U11.AB5(MMC3_DAT7) ; also on sheet 26
OC0: U17.46(OVERCUR1Z) ; also on sheet 24
OC1: U17.47(OVERCUR2Z) ; also on sheet 24
OC2: U17.44(OVERCUR3Z) ; also on sheet 24
OC3: U17.43(OVERCUR0Z) ; also on sheet 24
P1_TRD[0]N: U15.3(TXRXM_A) ; also on sheet 11
P1_TRD[0]P: U15.2(TXRXP_A) ; also on sheet 11
P1_TRD[1]N: U15.6(TXRXM_B) ; also on sheet 11
P1_TRD[1]P: U15.5(TXRXP_B) ; also on sheet 11
P1_TRD[2]N: U15.8(TXRXM_C) ; also on sheet 11
P1_TRD[2]P: U15.7(TXRXP_C) ; also on sheet 11
P1_TRD[3]N: U15.11(TXRXM_D) ; also on sheet 11
P1_TRD[3]P: U15.10(TXRXP_D) ; also on sheet 11
PUSB_RXN0: C242.1 U11.AF12(USB_RXN0)
PUSB_RXP0: C241.1 U11.AE12(USB_RXP0)
PUSB_TXN0: C244.1 U11.AC11(USB_TXN0)
PUSB_TXP0: C239.1 U11.AD11(USB_TXP0)
R_EMAC[1]_RXC: R100.2 R106.2 U15.35(RX_CLK)
R_EMAC[1]_RXCTL: R99.2 R105.2 U15.33(RX_DV)
R_EMAC[1]_RXD0: R101.2 R107.2 U15.32(RXD0)
R_EMAC[1]_RXD1: R102.2 R108.2 U15.31(RXD1)
R_EMAC[1]_RXD2: R103.2 R109.2 U15.28(RXD2)
R_EMAC[1]_RXD3: R104.2 R110.2 U15.27(RXD3)
R_EMAC[1]_TXC: R112.2 U15.24(GTX_CLK)
R_EMAC[1]_TXCTL: R111.2 U15.25(TX_EN)
R_EMAC[1]_TXD0: R113.2 U15.19(TXD0)
R_EMAC[1]_TXD1: R114.2 U15.20(TXD1)
R_EMAC[1]_TXD2: R115.2 U15.21(TXD2)
R_EMAC[1]_TXD3: R118.2 U15.22(TXD3)
RHDMI_TX0+: C555.1 U11.AH17(HDMI1_DATA0Y)
RHDMI_TX0-: C556.1 U11.AG17(HDMI1_DATA0X)
RHDMI_TX1+: C553.1 U11.AH18(HDMI1_DATA1Y)
RHDMI_TX1-: C554.1 U11.AG18(HDMI1_DATA1X)
RHDMI_TX2+: C551.1 U11.AH19(HDMI1_DATA2Y)
RHDMI_TX2-: C552.1 U11.AG19(HDMI1_DATA2X)
RHDMI_TXC+: C557.1 U11.AH16(HDMI1_CLOCKY)
RHDMI_TXC-: C558.1 U11.AG16(HDMI1_CLOCKX)
RIGHT_IN: C256.2 D11.2 P9.3 R234.1
RIGHT_OUT: C251.2 D9.2 P8.3 R228.1
RSTOUTn: U18.31(RESETn) U22.K5(~{RST}) ; also on sheet 3 8 25 26
SCL_HUB: R393.2 U17.38(SCL_SMBCLK)
SDA_HUB: R394.2 U17.37(SDA_SMBDAT)
SS_SUSPEND: R243.2 U17.45(HS_SUSPEND)
TIMER1: U11.E21(TIMER1) ; also on sheet 26
TIMER2: U11.F20(TIMER2) ; also on sheet 26
TIMER3: U11.F21(TIMER3) ; also on sheet 26
U15_41: R120.1 U15.41(CLK125_NDO)
U16_FB: R201.2 R203.1 U16.8(FB)
U17_A17: R207.2 U17.40(FULLPWRMGMTZ_SMBA1)
U17_A41: R209.2 U17.42(GANGED/SMBA2/HS_UP)
U21_VCCA: C523.1 C524.1 FB12.2 R237.1 R245.1 R246.1 R247.2 R248.2 U21.23(VCCA)
UART3_RXD: U20.6(1Y) ; also on sheet 27
UART3_TXD: U20.5(2A) ; also on sheet 27
UART8_CTSN: U11.G16(UART8_CTSN) ; also on sheet 26
UART8_RTSN: U11.D17(UART8_RTSN) ; also on sheet 26
UART8_RXD: U11.C18(UART8_RXD) ; also on sheet 26
UART8_TXD: U11.A21(UART8_TXD) ; also on sheet 26
UART9_CTSN: U11.AB3(UART9_CTSN) ; also on sheet 26
UART9_RTSN: U11.AA4(UART9_RTSN) ; also on sheet 26
UART9_RXD: U11.AA3(UART9_RXD) ; also on sheet 26
UART9_TXD: U11.AB9(UART9_TXD) ; also on sheet 26
USB1_DM: U11.AC12(USB1_DM) U17.54(USB_DM_UP)
USB1_DP: U11.AD12(USB1_DP) U17.53(USB_DP_UP)
USB1_DRVBUS_R: R330.1 U11.AB10(USB1_DRVVBUS)
USB1_DRVVBUS: R329.2 R330.2 U17.48(USB_VBUS)
USB1_ID: R205.1 U11.C27(GPIO7_25)
USB2_DM: D40.2(D-) P7.2(D-) U11.AF11(USB2_DM)
USB2_DP: D40.1(D+) P7.3(D+) U11.AE11(USB2_DP)
USB2_VBUS: C479.1 D42.1(IO) P7.1(VB) ; also on sheet 3
USB_DM0: U17.2(USB_DM_DN1) ; also on sheet 24
USB_DM1: U17.10(USB_DM_DN2) ; also on sheet 24
USB_DM2: U17.18(USB_DM_DN3) ; also on sheet 24
USB_DM3: U17.25(USB_DM_DN4) ; also on sheet 24
USB_DP0: U17.1(USB_DP_DN1) ; also on sheet 24
USB_DP1: U17.9(USB_DP_DN2) ; also on sheet 24
USB_DP2: U17.17(USB_DP_DN3) ; also on sheet 24
USB_DP3: U17.24(USB_DP_DN4) ; also on sheet 24
USB_R1: R206.2 U17.64(USB_R1)
USB_RXM0: U17.7(USB_SSRXM_DN1) ; also on sheet 24
USB_RXM1: U17.15(USB_SSRXM_DN2) ; also on sheet 24
USB_RXM2: U17.23(USB_SSRXM_DN3) ; also on sheet 24
USB_RXP0: U17.6(USB_SSRXP_DN1) ; also on sheet 24
USB_RXP1: U17.14(USB_SSRXP_DN2) ; also on sheet 24
USB_RXP2: U17.22(USB_SSRXP_DN3) ; also on sheet 24
USB_SSRXM0: C244.2 U17.59(USB_SSRXM_UP)
USB_SSRXP0: C239.2 U17.58(USB_SSRXP_UP)
USB_SSTXM0: C242.2 U17.56(USB_SSTXM_UP)
USB_SSTXP0: C241.2 U17.55(USB_SSTXP_UP)
USB_TXM0: U17.4(USB_SSTXM_DN1) ; also on sheet 24
USB_TXM1: U17.12(USB_SSTXM_DN2) ; also on sheet 24
USB_TXM2: U17.20(USB_SSTXM_DN3) ; also on sheet 24
USB_TXP0: U17.3(USB_SSTXP_DN1) ; also on sheet 24
USB_TXP1: U17.11(USB_SSTXP_DN2) ; also on sheet 24
USB_TXP2: U17.19(USB_SSTXP_DN3) ; also on sheet 24
VDAC_3V3: C247.1 C252.1 C260.1 L12.3 L13.1 L14.1 L15.1 U19.1(IN)
VOUT1_CLK: R149.2 ; also on sheet 26
VOUT1_D0: R124.2 ; also on sheet 26
VOUT1_D1: R125.2 ; also on sheet 26
VOUT1_D2: R126.2 ; also on sheet 26
VOUT1_D3: R127.2 ; also on sheet 26
VOUT1_D4: R128.2 ; also on sheet 26
VOUT1_D5: R129.2 ; also on sheet 26
VOUT1_D6: R130.2 ; also on sheet 26
VOUT1_D7: R131.2 ; also on sheet 26
VOUT1_D8: R132.2 ; also on sheet 26
VOUT1_D9: R133.2 ; also on sheet 26
VOUT1_D10: R134.2 ; also on sheet 26
VOUT1_D11: R135.2 ; also on sheet 26
VOUT1_D12: R136.2 ; also on sheet 26
VOUT1_D13: R138.2 ; also on sheet 26
VOUT1_D14: R139.2 ; also on sheet 26
VOUT1_D15: R140.2 ; also on sheet 26
VOUT1_D16: R141.2 ; also on sheet 26
VOUT1_D17: R142.2 ; also on sheet 26
VOUT1_D18: R143.2 ; also on sheet 26
VOUT1_D19: R144.2 ; also on sheet 26
VOUT1_D20: R145.2 ; also on sheet 26
VOUT1_D21: R146.2 ; also on sheet 26
VOUT1_D22: R147.2 ; also on sheet 26
VOUT1_D23: R148.2 ; also on sheet 26
VOUT1_DE: R150.2 ; also on sheet 26
VOUT1_HSYNC: R152.2 ; also on sheet 26
VOUT1_RD0: R124.1 U11.F11(VOUT1_D0)
VOUT1_RD1: R125.1 U11.G10(VOUT1_D1)
VOUT1_RD2: R126.1 U11.F10(VOUT1_D2)
VOUT1_RD3: R127.1 U11.G11(VOUT1_D3)
VOUT1_RD4: R128.1 U11.E9(VOUT1_D4)
VOUT1_RD5: R129.1 U11.F9(VOUT1_D5)
VOUT1_RD6: R130.1 U11.F8(VOUT1_D6)
VOUT1_RD7: R131.1 U11.E7(VOUT1_D7)
VOUT1_RD8: R132.1 U11.E8(VOUT1_D8)
VOUT1_RD9: R133.1 U11.D9(VOUT1)
VOUT1_RD10: R134.1 U11.D7(VOUT1_D10)
VOUT1_RD11: R135.1 U11.D8(VOUT1_D11)
VOUT1_RD12: R136.1 U11.A5(VOUT1_D12)
VOUT1_RD13: R138.1 U11.C6(VOUT1_D13)
VOUT1_RD14: R139.1 U11.C8(VOUT1_D14)
VOUT1_RD15: R140.1 U11.C7(VOUT1_D15)
VOUT1_RD16: R141.1 U11.B7(VOUT1_D16)
VOUT1_RD17: R142.1 U11.B8(VOUT1_D17)
VOUT1_RD18: R143.1 U11.A7(VOUT1_D18)
VOUT1_RD19: R144.1 U11.A8(VOUT1_D19)
VOUT1_RD20: R145.1 U11.C9(VOUT1_D20)
VOUT1_RD21: R146.1 U11.A9(VOUT1_D21)
VOUT1_RD22: R147.1 U11.B9(VOUT1_D22)
VOUT1_RD23: R148.1 U11.A10(VOUT1_D23)
VOUT1_RDCLK: R149.1 U11.D11(VOUT1_CLK)
VOUT1_RDE: R150.1 U11.B10(VOUT1_DE)
VOUT1_RHSYNC: R152.1 U11.C11(VOUT1_HSYNC)
VOUT1_RVSYNC: R153.1 U11.E11(VOUT1_VSYNC)
VOUT1_VSYNC: R153.2 ; also on sheet 26
VUSB_3V3: C236.1 C237.1 C238.1 U11.AA12(VDDA33V_USB1) U11.Y12(VDDA33V_USB2) ; also on sheet 4
ZQ1_HI: R275.1 U24.L8(ZQ)
ZQ1_LO: R276.1 U23.L8(ZQ)
N29512994: J3.2 R239.2 R444.1
N29513031: J4.2 R182.2 R442.1
N29513057: J6.2 R187.2 R443.1
N29735394: R328.1 U17.41(PWRCTL_POL)
N30634730: C264.1 FB13.2 U21.10(VCC_5V)
N30807727: C551.2 FL1.4 R445.1
N30807730: C552.2 FL1.1 R446.1
N30807733: C553.2 FL2.4 R447.1
N30807736: C554.2 FL2.1 R448.1
N30807739: C555.2 FL3.4 R452.1
N30807742: C556.2 FL3.1 R450.1
N30807745: C557.2 FL4.4 R449.1
N30807748: C558.2 FL4.1 R451.1

Not connected (* = marked no-connect by the designer): D20 2(NC.2); D21 2(NC.2); D22 2(NC.2); D23 2(NC.2) 3(IO1); P7 4(ID)*; P8 4; P9 4; P10 2* 3* 6*; P11 14(NC.14)* MTG1* MTG2*; P12 11(GND3)* 12(GND4)* 15(GND7)* 16(GND8)*; U11 AC10(USB2_DRVVBUS)* B24(GPIO7_17)* E25(GPIO7_24)* V23(DDR1_ECC_D1)* V24(DDR1_ECC_D5)* V25(DDR1_ECC_D6)* V26(DDR1_DQM_ECC)* W19(DDR1_ECC_D2)* W22(DDR1_ECC_D0)* W23(DDR1_ECC_D3)* Y25(DDR1_ECC_D4)* Y26(DDR1_ECC_D7)*; U15 13(NC1)* 47(NC)*; U16 3(~{PG})*; U17 26(USB_SSTXP_DN4)* 27(USB_SSTXM_DN4)* 29(USB_SSRXP_DN4)* 30(USB_SSRXM_DN4)* 39(SS_SUSPEND)* 49(TEST)* 60(NC)*; U18 10(IN1LP)* 11(IM1LM)* 12(IN1RP)* 13(IN1RM)* 15(MICBIAS)* 19(HPLOUT)* 20(HPLCOM)* 22(HPRCOM)* 23(HPROUT)* 28(LEFT_LOM)* 30(RIGHT_ROM)*; U19 4(NC/FB)*; U21 14(CLK-) 15(CLK+) 16(D0-) 17(D0+) 19(D1-) 20(D1+) 21(D2-) 22(D2+); U22 A1(NC11)* A2(NC4)* A6(NC5)* A7(NC6)* A8(NC7)* A9(NC18)* A10(NC95)* A11(NC94)* A12(NC93)* A13(NC92)* A14(NC91)* B1(NC90)* B7(NC89)* B8(NC74)* B9(NC53)* B10(NC52)* B11(NC51)* B12(NC50)* B13(NC49)* B14(NC19)* C1(NC34)* C3(NC33)* C5(NC32)* C7(NC31)* C8(NC30)* C9(NC29)* C10(NC25)* C11(NC23)* C12(NC22)* C13(NC21)* C14(NC20)* D1(NC48)* D2(NC46)* D3(NC39)* D4(NC38)* D12(NC37)* D13(NC36)* D14(NC35)* E1(NC1)* E2(NC2)* E3(NC3)* E5(NC121)* E8(NC8)* E9(NC9)* E10(NC10)* E12(NC12)* E13(NC13)* E14(NC14)* F1(NC15)* F2(NC16)* F3(NC17)* F10(NC24)* F12(NC26)* F13(NC27)* F14(NC28)* G1(NC88)* G2(NC81)* G3(NC79)* G10(NC78)* G12(NC40)* G13(NC41)* G14(NC42)* H1(NC43)* H2(NC44)* H3(NC45)* H5(NC47)* H12(NC54)* H13(NC55)* H14(NC56)* J1(NC57)* J2(NC58)* J3(NC59)* J5(NC60)* J12(NC117)* J13(NC69)* J14(NC70)* K1(NC71)* K2(NC72)* K3(NC73)* K6(NC123)* K7(NC77)* K10(NC80)* K12(NC82)* K13(NC83)* K14(NC84)* L1(NC85)* L2(NC86)* L3(NC87)* L12(NC96)* L13(NC97)* L14(NC98)* M1(NC99)* M2(NC100)* M3(NC101)* M7(NC105)* M8(NC106)* M9(NC107)* M10(NC108)* M11(NC109)* M12(NC110)* M13(NC111)* M14(NC112)* N1(NC113)* N3(NC115)* N6(NC122)* N7(NC118)* N8(NC119)* N9(NC120)* N10(NC75)* N11(NC76)* N12(NC68)* N13(NC67)* N14(NC66)* P1(NC65)* P2(NC64)* P7(NC63)* P8(NC61)* P9(NC62)* P10(NC114)* P11(NC104)* P12(NC103)* P13(NC102)* P14(NC116)*; U23 J1(NC.J1)* J9(NC.J9)* L1(NC.L1)* L9(NC.L9)*; U24 J1(NC.J1)* J9(NC.J9)* L1(NC.L1)* L9(NC.L9)*

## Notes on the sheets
sheet 12
- PHYAD 0X02
- ETHERNET PORT 1
sheet 13
- Optional Boot Options. Strapped for
  SD then eMMC boot by default.
- 1-2
- 2-3
- BOOT
  from SD
  then
  eMMC
- J3
- X
- J4
- X
- J6
- X
- J3
- X
- BOOT
  from
  UART
- J4
- X
- J6
- X
- J3
- X
- BOOT from
  SATA then
  SD
- J4
- X
- J6
- X
- 1
- 0
- 0
- 0
- 0
- 0
- 0
- 1
sheet 14
- USB CLIENT PORT
sheet 15
- I2C1 ADDRESS 0X18
- DEBUG HEADER
- FTDI USB TO SERIAL CABLE
- DENOTE PIN 1 ON THE
  SILKSCREEN AND ADD
  TEXT "DEBUG HEADER"
sheet 16
- 55mA MAX
